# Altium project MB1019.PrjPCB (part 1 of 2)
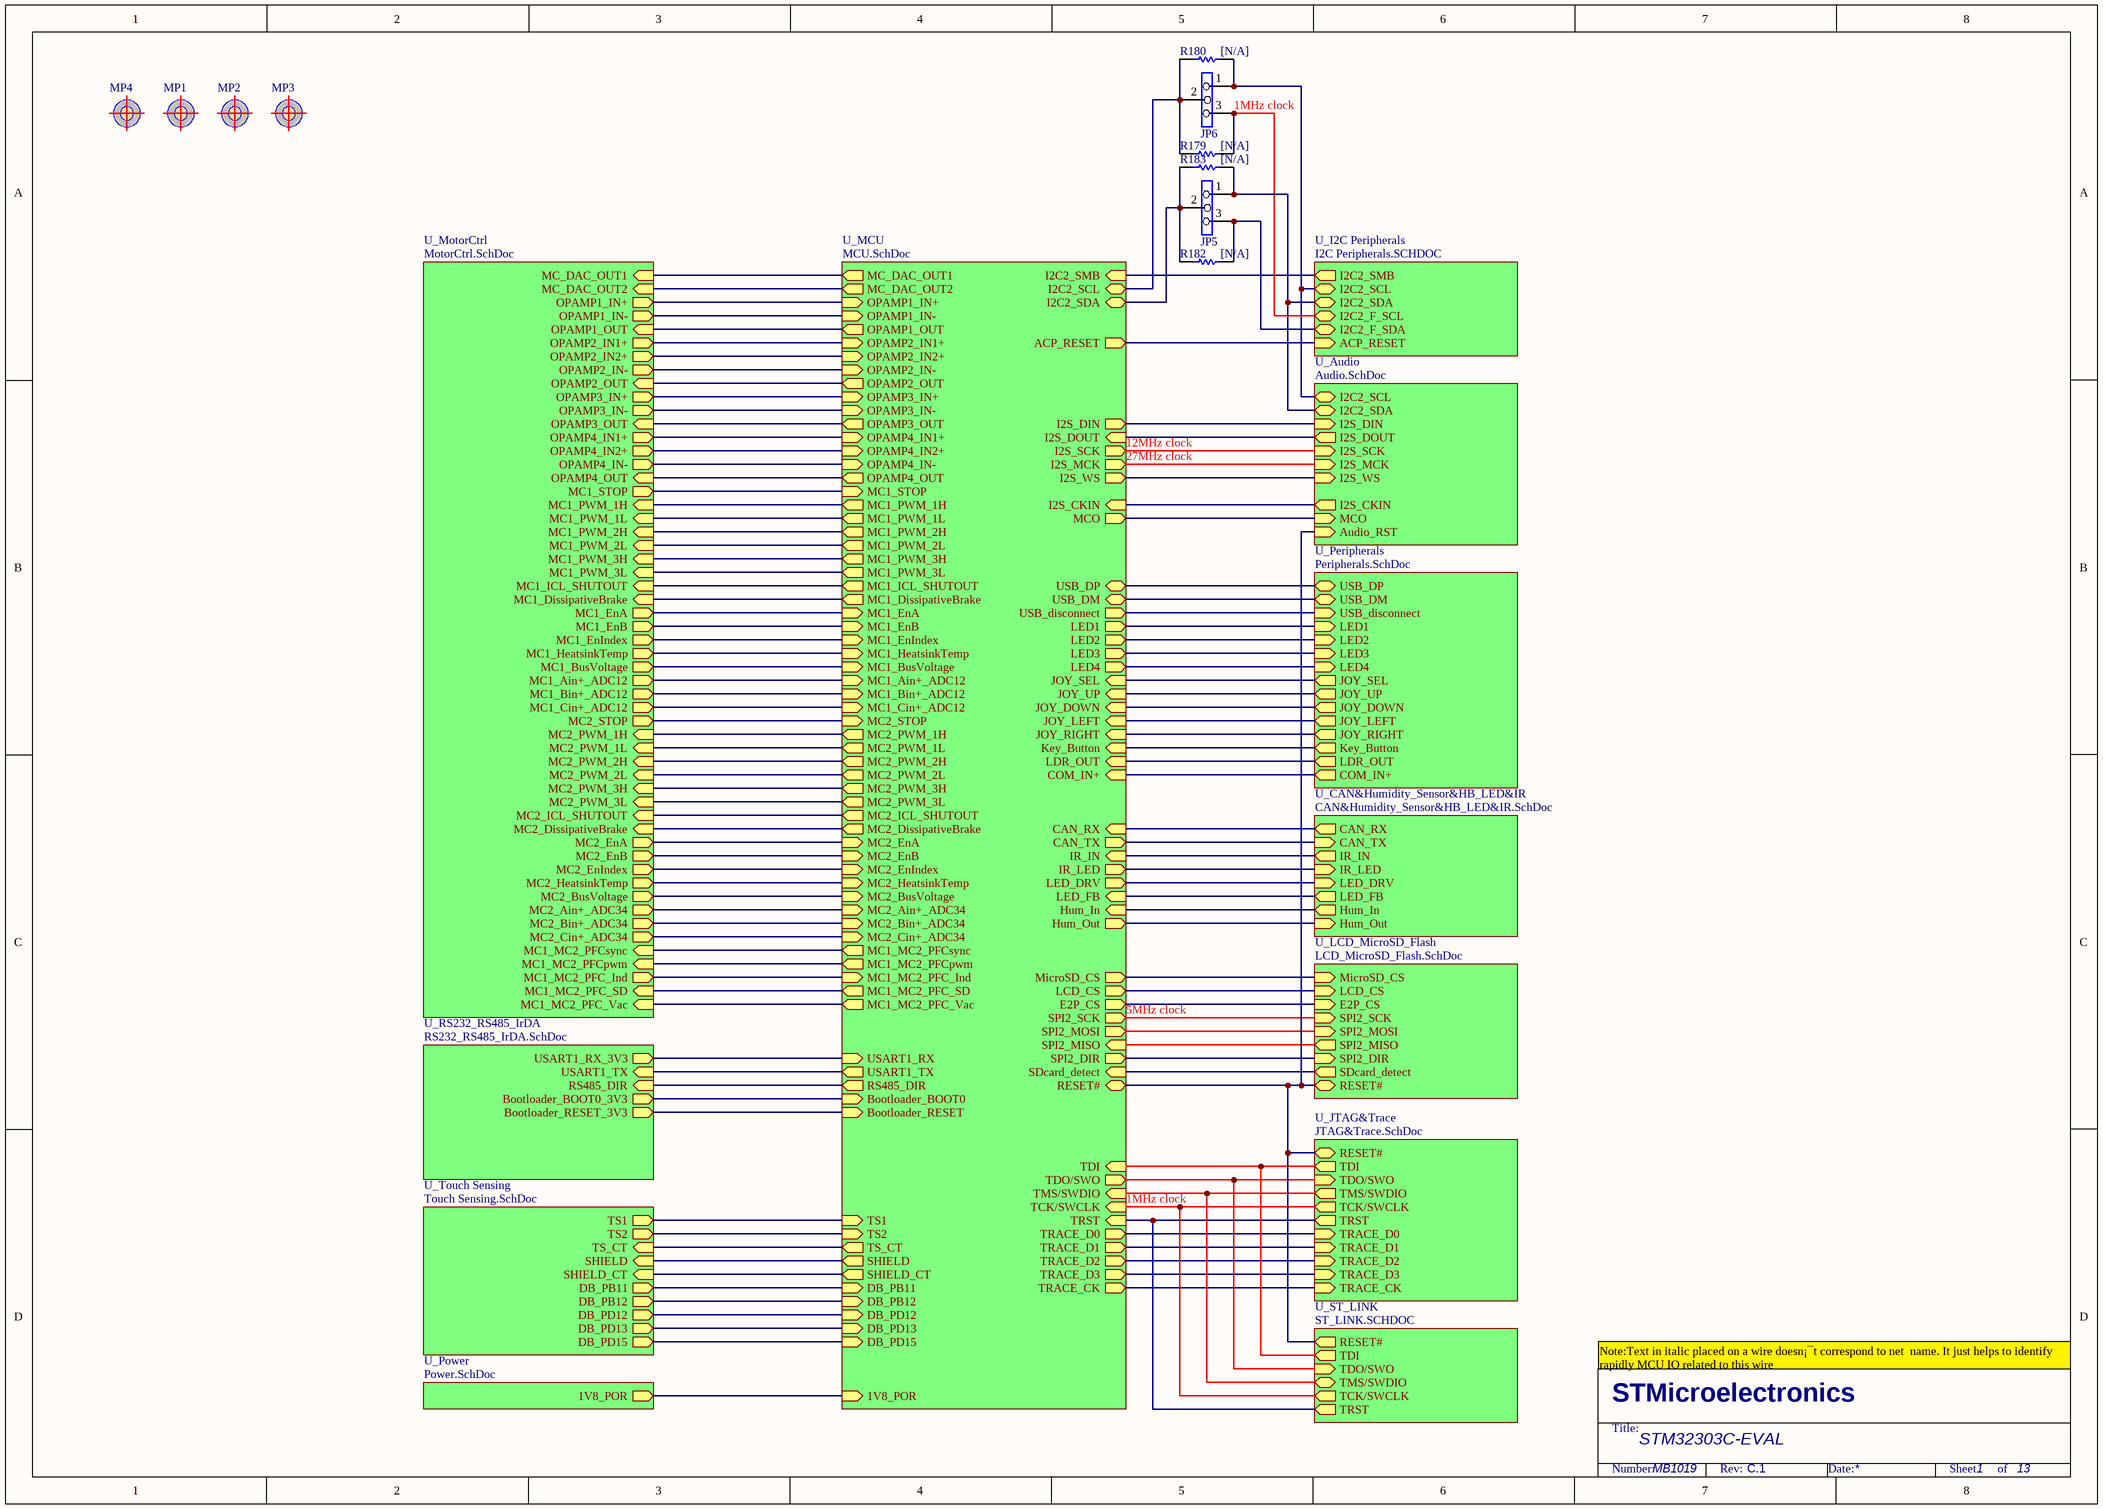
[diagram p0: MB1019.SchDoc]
13 sheets, 557 parts. Net scope: hierarchical (ports join the sheet entries above them; power ports are global).
Sheets:
  MB1019.SchDoc
    U_MCU = MCU.SchDoc
    U_MotorCtrl = MotorCtrl.SchDoc
    U_RS232_RS485_IrDA = RS232_RS485_IrDA.SchDoc
    U_Touch Sensing = Touch Sensing.SchDoc
    U_Peripherals = Peripherals.SchDoc
    U_CAN&Humidity_Sensor&HB_LED&IR = CAN&Humidity_Sensor&HB_LED&IR.SchDoc
    U_JTAG&Trace = JTAG&Trace.SchDoc
    U_ST_LINK = ST_LINK.SCHDOC
    U_Power = Power.SchDoc
    U_Audio = Audio.SchDoc
    U_I2C Peripherals = I2C Peripherals.SCHDOC
    U_LCD_MicroSD_Flash = LCD_MicroSD_Flash.SchDoc

## Sheet MB1019.SchDoc
size A3; Revision: C.1

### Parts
JP5  (no value)  [SIP3]
JP6  (no value)  [SIP3]
MP1  (no value)  [markpoint_1.0]
MP2  (no value)  [markpoint_1.0]
MP3  (no value)  [markpoint_1.0]
MP4  (no value)  [markpoint_1.0]
R179  [N/A]  [0603R]
R180  [N/A]  [0603R]
R182  [N/A]  [0603R]
R183  [N/A]  [0603R]

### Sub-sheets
U_Audio = Audio.SchDoc: I2S_WS (in), I2S_DIN (in), I2S_SCK (in), Audio_RST (in), I2S_MCK (in), MCO (in), I2S_CKIN (out), I2C2_SCL (bidir), I2C2_SDA (bidir), I2S_DOUT (out)
U_CAN&Humidity_Sensor&HB_LED&IR = CAN&Humidity_Sensor&HB_LED&IR.SchDoc: CAN_TX (in), CAN_RX (out), IR_LED (in), IR_IN (out), LED_DRV (in), LED_FB (out), Hum_Out (in), Hum_In (out)
U_I2C Peripherals = I2C Peripherals.SCHDOC: I2C2_SCL (bidir), I2C2_SDA (bidir), I2C2_SMB (out), I2C2_F_SDA (bidir), I2C2_F_SCL (bidir), ACP_RESET (in)
U_JTAG&Trace = JTAG&Trace.SchDoc: TDI (out), RESET# (bidir), TRACE_D3 (in), TRACE_D2 (in), TRACE_D1 (in), TRACE_D0 (in), TRACE_CK (in), TRST (out), TMS/SWDIO (out), TCK/SWCLK (out), TDO/SWO (in)
U_LCD_MicroSD_Flash = LCD_MicroSD_Flash.SchDoc: MicroSD_CS (in), SPI2_SCK (in), SPI2_MOSI (in), LCD_CS (in), SDcard_detect (out), RESET# (bidir), E2P_CS (in), SPI2_MISO (out), SPI2_DIR (in)
U_MCU = MCU.SchDoc: USB_DM (bidir), I2C2_SCL (bidir), I2C2_SDA (bidir), TMS/SWDIO (in), TCK/SWCLK (in), TDI (in), COM_IN+ (in), TDO/SWO (out), TRST (in), IR_IN (in), IR_LED (out), SPI2_MISO (in), SPI2_MOSI (out), RESET# (bidir), LDR_OUT (in), SPI2_SCK (out), USART1_RX (in), USART1_TX (out), LED4 (out), LED3 (out), LED1 (out), LED2 (out), Bootloader_BOOT0 (in), Bootloader_RESET (in), I2C2_SMB (in), USB_DP (bidir), CAN_RX (in), CAN_TX (out), MicroSD_CS (out), TRACE_D0 (out), TRACE_D1 (out), Key_Button (in), JOY_SEL (in), JOY_DOWN (in), JOY_LEFT (in), JOY_UP (in), JOY_RIGHT (in), TRACE_CK (out), E2P_CS (out), LCD_CS (out), TRACE_D2 (out), TRACE_D3 (out), SDcard_detect (in), DB_PD13 (in), DB_PD15 (in), 1V8_POR (in), USB_disconnect (out), MC2_HeatsinkTemp (in), OPAMP1_IN+ (in), OPAMP2_IN1+ (in), OPAMP3_IN+ (in), OPAMP3_OUT (out), OPAMP3_IN- (in), MC2_EnA (in), MC2_STOP (in), MC2_EnIndex (in), OPAMP4_IN- (in), OPAMP4_OUT (out), OPAMP4_IN1+ (in), MC1_Cin+_ADC12 (in), MC1_Ain+_ADC12 (in), MC1_Bin+_ADC12 (in), MC2_PWM_1H (out), MC2_PWM_2H (out), MC2_PWM_3H (out), MC2_PWM_1L (out), MC2_PWM_2L (out), MC2_PWM_3L (out), MC1_MC2_PFC_SD (out), MC1_EnA (in), MC1_EnB (in), MC1_EnIndex (in), MC1_MC2_PFC_Ind (in), MC2_EnB (in), MC1_MC2_PFCsync (out), MC1_MC2_PFCpwm (out), MC1_ICL_SHUTOUT (out), MC1_DissipativeBrake (out), MC1_PWM_1H (out), MC1_PWM_2H (out), MC1_PWM_3H (out), MC1_PWM_1L (out), MC1_PWM_2L (out), MC1_PWM_3L (out), LED_DRV (out), MC1_STOP (in), LED_FB (in), MC1_HeatsinkTemp (in), MC2_ICL_SHUTOUT (out), MC2_DissipativeBrake (out), MC1_MC2_PFC_Vac (out), MC2_BusVoltage (in), MC_DAC_OUT1 (out), MC_DAC_OUT2 (out), OPAMP1_OUT (out), OPAMP1_IN- (in), OPAMP2_OUT (out), OPAMP4_IN2+ (in), OPAMP2_IN2+ (in), MC1_BusVoltage (in), RS485_DIR (out), Hum_Out (out), TS2 (in), Hum_In (in), I2S_WS (out), SHIELD (out), OPAMP2_IN- (in), MC2_Cin+_ADC34 (in), MC2_Ain+_ADC34 (in), MC2_Bin+_ADC34 (in), TS_CT (out), TS1 (in), DB_PB12 (in), SHIELD_CT (out), DB_PD12 (in), DB_PB11 (in), ACP_RESET (out), I2S_CKIN (in), MCO (out), I2S_DIN (out), I2S_SCK (out), I2S_MCK (out), I2S_DOUT (in), SPI2_DIR (out)
U_MotorCtrl = MotorCtrl.SchDoc: MC1_STOP (out), MC1_MC2_PFCsync (in), MC1_ICL_SHUTOUT (in), MC1_DissipativeBrake (in), MC1_MC2_PFCpwm (in), MC1_EnA (out), MC1_EnB (out), MC1_HeatsinkTemp (out), MC1_BusVoltage (out), MC1_EnIndex (out), MC1_PWM_1H (in), MC1_PWM_2H (in), MC1_PWM_3H (in), MC1_PWM_1L (in), MC1_PWM_2L (in), MC1_PWM_3L (in), MC1_MC2_PFC_Ind (out), MC1_MC2_PFC_Vac (in), MC1_MC2_PFC_SD (in), MC2_STOP (out), MC2_ICL_SHUTOUT (in), MC2_DissipativeBrake (in), MC2_EnA (out), MC2_EnB (out), MC2_HeatsinkTemp (out), MC2_BusVoltage (out), MC2_EnIndex (out), MC2_PWM_1H (in), MC2_PWM_2H (in), MC2_PWM_3H (in), MC2_PWM_1L (in), MC2_PWM_2L (in), MC2_PWM_3L (in), OPAMP1_IN+ (out), OPAMP1_IN- (out), OPAMP1_OUT (in), MC1_Ain+_ADC12 (out), MC_DAC_OUT2 (in), MC_DAC_OUT1 (in), OPAMP2_IN1+ (out), OPAMP2_IN- (out), OPAMP2_OUT (in), OPAMP2_IN2+ (out), OPAMP4_IN1+ (out), OPAMP4_IN- (out), OPAMP4_OUT (in), OPAMP4_IN2+ (out), OPAMP3_IN+ (out), OPAMP3_IN- (out), OPAMP3_OUT (in), MC1_Bin+_ADC12 (out), MC1_Cin+_ADC12 (out), MC2_Cin+_ADC34 (out), MC2_Bin+_ADC34 (out), MC2_Ain+_ADC34 (out)
U_Peripherals = Peripherals.SchDoc: JOY_SEL (out), JOY_DOWN (out), JOY_LEFT (out), JOY_RIGHT (out), JOY_UP (out), USB_DM (bidir), USB_DP (bidir), Key_Button (out), USB_disconnect (in), LDR_OUT (out), COM_IN+ (out), LED4 (in), LED3 (in), LED1 (in), LED2 (in)
U_Power = Power.SchDoc: 1V8_POR (out)
U_RS232_RS485_IrDA = RS232_RS485_IrDA.SchDoc: USART1_RX_3V3 (out), RS485_DIR (in), Bootloader_BOOT0_3V3 (out), Bootloader_RESET_3V3 (out), USART1_TX (in)
U_ST_LINK = ST_LINK.SCHDOC: TDI (out), TRST (out), TMS/SWDIO (bidir), TCK/SWCLK (out), TDO/SWO (in), RESET# (out)
U_Touch Sensing = Touch Sensing.SchDoc: TS1 (out), TS2 (out), SHIELD (in), SHIELD_CT (in), TS_CT (in), DB_PD13 (out), DB_PD15 (out), DB_PD12 (out), DB_PB11 (out), DB_PB12 (out)

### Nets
MC1_MC2_PFC_Ind: sheet U_MCU/MC1_MC2_PFC_Ind, sheet U_MotorCtrl/MC1_MC2_PFC_Ind
MC1_MC2_PFC_SD: sheet U_MCU/MC1_MC2_PFC_SD, sheet U_MotorCtrl/MC1_MC2_PFC_SD
MC1_MC2_PFC_Vac: sheet U_MCU/MC1_MC2_PFC_Vac, sheet U_MotorCtrl/MC1_MC2_PFC_Vac
MC1_MC2_PFCpwm: sheet U_MCU/MC1_MC2_PFCpwm, sheet U_MotorCtrl/MC1_MC2_PFCpwm
MC1_MC2_PFCsync: sheet U_MCU/MC1_MC2_PFCsync, sheet U_MotorCtrl/MC1_MC2_PFCsync
PA1: sheet U_MCU/OPAMP1_IN+, sheet U_MotorCtrl/OPAMP1_IN+
PA2: sheet U_MCU/OPAMP1_OUT, sheet U_MotorCtrl/OPAMP1_OUT
PA3: sheet U_MCU/OPAMP1_IN-, sheet U_MotorCtrl/OPAMP1_IN-
PA5: sheet U_MCU/MC_DAC_OUT2, sheet U_MotorCtrl/MC_DAC_OUT2
PA6: sheet U_MCU/OPAMP2_OUT, sheet U_MotorCtrl/OPAMP2_OUT
PA7: sheet U_MCU/OPAMP2_IN1+, sheet U_MotorCtrl/OPAMP2_IN1+
PA8: sheet U_MCU/MCO, sheet U_Audio/MCO
PA10: JP5.2 R182.2 R183.2 ; sheet U_MCU/I2C2_SDA
PA11: sheet U_MCU/USB_DM, sheet U_Peripherals/USB_DM
PA12: sheet U_MCU/USB_DP, sheet U_Peripherals/USB_DP
PA13: sheet U_MCU/TMS/SWDIO, sheet U_JTAG&Trace/TMS/SWDIO, sheet U_ST_LINK/TMS/SWDIO
PA14: sheet U_MCU/TCK/SWCLK, sheet U_JTAG&Trace/TCK/SWCLK, sheet U_ST_LINK/TCK/SWCLK
PA15: sheet U_MCU/TDI, sheet U_JTAG&Trace/TDI, sheet U_ST_LINK/TDI
PB1: sheet U_MCU/OPAMP3_OUT, sheet U_MotorCtrl/OPAMP3_OUT
PB2: sheet U_MCU/1V8_POR, sheet U_Power/1V8_POR
PB3: sheet U_MCU/TDO/SWO, sheet U_JTAG&Trace/TDO/SWO, sheet U_ST_LINK/TDO/SWO
PB4: sheet U_MCU/TRST, sheet U_JTAG&Trace/TRST, sheet U_ST_LINK/TRST
PB5: sheet U_MCU/JOY_LEFT, sheet U_Peripherals/JOY_LEFT
PB6: sheet U_MCU/MC2_EnA, sheet U_MotorCtrl/MC2_EnA
PB7: sheet U_MCU/MC2_STOP, sheet U_MotorCtrl/MC2_STOP
PB9: sheet U_MCU/IR_LED, sheet U_CAN&Humidity_Sensor&HB_LED&IR/IR_LED
PB10: sheet U_MCU/OPAMP4_IN-, sheet U_MotorCtrl/OPAMP4_IN-
PB13: sheet U_MCU/OPAMP4_IN2+, sheet U_MotorCtrl/OPAMP4_IN2+
PB14: sheet U_MCU/SPI2_MISO, sheet U_LCD_MicroSD_Flash/SPI2_MISO
PB15: sheet U_MCU/SPI2_MOSI, sheet U_LCD_MicroSD_Flash/SPI2_MOSI
PC0: sheet U_MCU/MC1_Cin+_ADC12, sheet U_MotorCtrl/MC1_Cin+_ADC12
PC2: sheet U_MCU/MC1_Ain+_ADC12, sheet U_MotorCtrl/MC1_Ain+_ADC12
PC3: sheet U_MCU/MC1_Bin+_ADC12, sheet U_MotorCtrl/MC1_Bin+_ADC12
PC4: sheet U_MCU/USART1_TX, sheet U_RS232_RS485_IrDA/USART1_TX
PC5: sheet U_MCU/OPAMP2_IN-, sheet U_MotorCtrl/OPAMP2_IN-
PC7: sheet U_MCU/MC2_PWM_2H, sheet U_MotorCtrl/MC2_PWM_2H
PC9: sheet U_MCU/I2S_CKIN, sheet U_Audio/I2S_CKIN
PC13: sheet U_MCU/JOY_SEL, sheet U_Peripherals/JOY_SEL
PD0: sheet U_MCU/CAN_RX, sheet U_CAN&Humidity_Sensor&HB_LED&IR/CAN_RX
PD1: sheet U_MCU/CAN_TX, sheet U_CAN&Humidity_Sensor&HB_LED&IR/CAN_TX
PD3: sheet U_MCU/MC1_EnA, sheet U_MotorCtrl/MC1_EnA
PD4: sheet U_MCU/MC1_EnB, sheet U_MotorCtrl/MC1_EnB
PD5: sheet U_MCU/JOY_DOWN, sheet U_Peripherals/JOY_DOWN
PD6: sheet U_MCU/JOY_RIGHT, sheet U_Peripherals/JOY_RIGHT
PD10: sheet U_MCU/MC2_Cin+_ADC34, sheet U_MotorCtrl/MC2_Cin+_ADC34
PD11: sheet U_MCU/MC2_Ain+_ADC34, sheet U_MotorCtrl/MC2_Ain+_ADC34
PE0: sheet U_MCU/LCD_CS, sheet U_LCD_MicroSD_Flash/LCD_CS
PE1: sheet U_MCU/USART1_RX, sheet U_RS232_RS485_IrDA/USART1_RX_3V3
PE6: sheet U_MCU/TRACE_D3, sheet U_JTAG&Trace/TRACE_D3
PE7: sheet U_MCU/JOY_UP, sheet U_Peripherals/JOY_UP
PE12: sheet U_MCU/MC1_PWM_3L, sheet U_MotorCtrl/MC1_PWM_3L
PE14: sheet U_MCU/ACP_RESET, sheet U_MCU/SPI2_DIR, sheet U_I2C Peripherals/ACP_RESET, sheet U_LCD_MicroSD_Flash/SPI2_DIR
PF4: sheet U_MCU/MC1_HeatsinkTemp, sheet U_MotorCtrl/MC1_HeatsinkTemp
PF6: JP6.2 R179.2 R180.2 ; sheet U_MCU/I2C2_SCL
PF9: sheet U_MCU/SPI2_SCK, sheet U_LCD_MicroSD_Flash/SPI2_SCK
PF10: sheet U_MCU/MC2_DissipativeBrake, sheet U_MotorCtrl/MC2_DissipativeBrake
RESET#: sheet U_MCU/RESET#, sheet U_JTAG&Trace/RESET#, sheet U_ST_LINK/RESET#, sheet U_Audio/Audio_RST, sheet U_LCD_MicroSD_Flash/RESET#
NetC2_2: sheet U_MCU/MC1_STOP, sheet U_MotorCtrl/MC1_STOP
NetC3_1: sheet U_MCU/MC1_BusVoltage, sheet U_MotorCtrl/MC1_BusVoltage
NetC13_2: sheet U_MCU/MC1_EnIndex, sheet U_MotorCtrl/MC1_EnIndex
NetC14_1: sheet U_MCU/MC2_BusVoltage, sheet U_MotorCtrl/MC2_BusVoltage
NetC19_2: sheet U_MCU/MC2_HeatsinkTemp, sheet U_MotorCtrl/MC2_HeatsinkTemp
NetC21_1: sheet U_MCU/OPAMP4_OUT, sheet U_MotorCtrl/OPAMP4_OUT
NetC27_2: sheet U_MCU/MC2_EnB, sheet U_MotorCtrl/MC2_EnB
NetC28_2: sheet U_MCU/MC2_EnIndex, sheet U_MotorCtrl/MC2_EnIndex
NetC29_2: sheet U_MCU/OPAMP3_IN-, sheet U_MotorCtrl/OPAMP3_IN-
NetC52_2: sheet U_MCU/TS_CT, sheet U_Touch Sensing/TS_CT
NetC68_1: sheet U_MCU/LED_FB, sheet U_CAN&Humidity_Sensor&HB_LED&IR/LED_FB
NetC133_1: sheet U_MCU/OPAMP2_IN2+, sheet U_MotorCtrl/OPAMP2_IN2+
NetC134_1: sheet U_MCU/OPAMP4_IN1+, sheet U_MotorCtrl/OPAMP4_IN1+
NetC136_1: sheet U_MCU/OPAMP3_IN+, sheet U_MotorCtrl/OPAMP3_IN+
NetCN2_3: sheet U_MCU/MC1_PWM_1H, sheet U_MotorCtrl/MC1_PWM_1H
NetCN2_5: sheet U_MCU/MC1_PWM_1L, sheet U_MotorCtrl/MC1_PWM_1L
NetCN2_7: sheet U_MCU/MC1_PWM_2H, sheet U_MotorCtrl/MC1_PWM_2H
NetCN2_9: sheet U_MCU/MC1_PWM_2L, sheet U_MotorCtrl/MC1_PWM_2L
NetCN2_11: sheet U_MCU/MC1_PWM_3H, sheet U_MotorCtrl/MC1_PWM_3H
NetCN2_21: sheet U_MCU/MC1_ICL_SHUTOUT, sheet U_MotorCtrl/MC1_ICL_SHUTOUT
NetCN2_23: sheet U_MCU/MC1_DissipativeBrake, sheet U_MotorCtrl/MC1_DissipativeBrake
NetCN4_3: sheet U_MCU/MC2_PWM_1H, sheet U_MotorCtrl/MC2_PWM_1H
NetCN4_5: sheet U_MCU/MC2_PWM_1L, sheet U_MotorCtrl/MC2_PWM_1L
NetCN4_9: sheet U_MCU/MC2_PWM_2L, sheet U_MotorCtrl/MC2_PWM_2L
NetCN4_11: sheet U_MCU/MC2_PWM_3H, sheet U_MotorCtrl/MC2_PWM_3H
NetCN4_13: sheet U_MCU/MC2_PWM_3L, sheet U_MotorCtrl/MC2_PWM_3L
NetCN4_21: sheet U_MCU/MC2_ICL_SHUTOUT, sheet U_MotorCtrl/MC2_ICL_SHUTOUT
NetCN6_51: sheet U_MCU/DB_PB11, sheet U_Touch Sensing/DB_PB11
NetCN6_52: sheet U_MCU/DB_PB12, sheet U_Touch Sensing/DB_PB12
NetCN7_2: sheet U_MCU/DB_PD15, sheet U_Touch Sensing/DB_PD15
NetCN7_4: sheet U_MCU/DB_PD13, sheet U_Touch Sensing/DB_PD13
NetCN7_6: sheet U_MCU/DB_PD12, sheet U_Touch Sensing/DB_PD12
NetCN9_12: sheet U_MCU/TRACE_CK, sheet U_JTAG&Trace/TRACE_CK
NetCN9_18: sheet U_MCU/TRACE_D2, sheet U_JTAG&Trace/TRACE_D2
NetCN16_2: sheet U_MCU/MicroSD_CS, sheet U_LCD_MicroSD_Flash/MicroSD_CS
NetCN16_10: sheet U_MCU/SDcard_detect, sheet U_LCD_MicroSD_Flash/SDcard_detect
NetD2_1: sheet U_MCU/Bootloader_BOOT0, sheet U_RS232_RS485_IrDA/Bootloader_BOOT0_3V3
NetJP1_2: sheet U_MCU/I2C2_SMB, sheet U_I2C Peripherals/I2C2_SMB
NetJP5_1: JP5.1 R183.1 ; sheet U_Audio/I2C2_SDA, sheet U_I2C Peripherals/I2C2_SDA
NetJP5_3: JP5.3 R182.1 ; sheet U_I2C Peripherals/I2C2_F_SDA
NetJP6_1: JP6.1 R180.1 ; sheet U_Audio/I2C2_SCL, sheet U_I2C Peripherals/I2C2_SCL
NetJP6_3: JP6.3 R179.1 ; sheet U_I2C Peripherals/I2C2_F_SCL
NetJP10_2: sheet U_MCU/Bootloader_RESET, sheet U_RS232_RS485_IrDA/Bootloader_RESET_3V3
NetJP18_1: sheet U_MCU/I2S_MCK, sheet U_Audio/I2S_MCK
NetJP18_3: sheet U_MCU/IR_IN, sheet U_CAN&Humidity_Sensor&HB_LED&IR/IR_IN
NetJP19_2: sheet U_MCU/Hum_In, sheet U_CAN&Humidity_Sensor&HB_LED&IR/Hum_In
NetPG3SA_2: sheet U_MCU/MC_DAC_OUT1, sheet U_MotorCtrl/MC_DAC_OUT1
NetR4_1: sheet U_MCU/TRACE_D0, sheet U_JTAG&Trace/TRACE_D0
NetR6_1: sheet U_MCU/TRACE_D1, sheet U_JTAG&Trace/TRACE_D1
NetR10_2: sheet U_MCU/LDR_OUT, sheet U_Peripherals/LDR_OUT
NetR14_1: sheet U_MCU/COM_IN+, sheet U_Peripherals/COM_IN+
NetR16_2: sheet U_MCU/I2S_WS, sheet U_Audio/I2S_WS
NetR18_2: sheet U_MCU/USB_disconnect, sheet U_Peripherals/USB_disconnect
NetR24_1: sheet U_MCU/LED1, sheet U_Peripherals/LED1
NetR26_1: sheet U_MCU/LED2, sheet U_Peripherals/LED2
NetR28_1: sheet U_MCU/LED3, sheet U_Peripherals/LED3
NetR30_1: sheet U_MCU/LED4, sheet U_Peripherals/LED4
NetR32_1: sheet U_MCU/LED_DRV, sheet U_CAN&Humidity_Sensor&HB_LED&IR/LED_DRV
NetR36_2: sheet U_MCU/SHIELD_CT, sheet U_Touch Sensing/SHIELD_CT
NetR38_2: sheet U_MCU/SHIELD, sheet U_Touch Sensing/SHIELD
NetR39_1: sheet U_MCU/MC2_Bin+_ADC34, sheet U_MotorCtrl/MC2_Bin+_ADC34
NetR42_1: sheet U_MCU/TS1, sheet U_Touch Sensing/TS1
NetR44_1: sheet U_MCU/TS2, sheet U_Touch Sensing/TS2
NetR50_1: sheet U_MCU/Hum_Out, sheet U_CAN&Humidity_Sensor&HB_LED&IR/Hum_Out
NetR52_1: sheet U_MCU/I2S_SCK, sheet U_Audio/I2S_SCK
NetR54_1: sheet U_MCU/I2S_DOUT, sheet U_Audio/I2S_DOUT
NetR56_1: sheet U_MCU/I2S_DIN, sheet U_Audio/I2S_DIN
NetR58_1: sheet U_MCU/E2P_CS, sheet U_LCD_MicroSD_Flash/E2P_CS
NetR111_1: sheet U_MCU/Key_Button, sheet U_Peripherals/Key_Button
NetR129_1: sheet U_MCU/RS485_DIR, sheet U_RS232_RS485_IrDA/RS485_DIR

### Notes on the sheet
- (near JP6) 1MHz clock
- 12MHz clock
- 27MHz clock
- 5MHz clock
- 1MHz clock
- Note:Text in italic placed on a wire doesn¡¯t correspond to net  name. It just helps to identify rapidly MCU IO related to this wire
- STM32303C-EVAL
- MB1019
- 1
- 13

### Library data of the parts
JP5 JP6 = Jumper3
MP1-MP4 = MARKPOINT
R179 R180 R182 R183 = Res1: Resistor; Value: 1K

## Sheet MCU.SchDoc
size A4; Revision: C.1
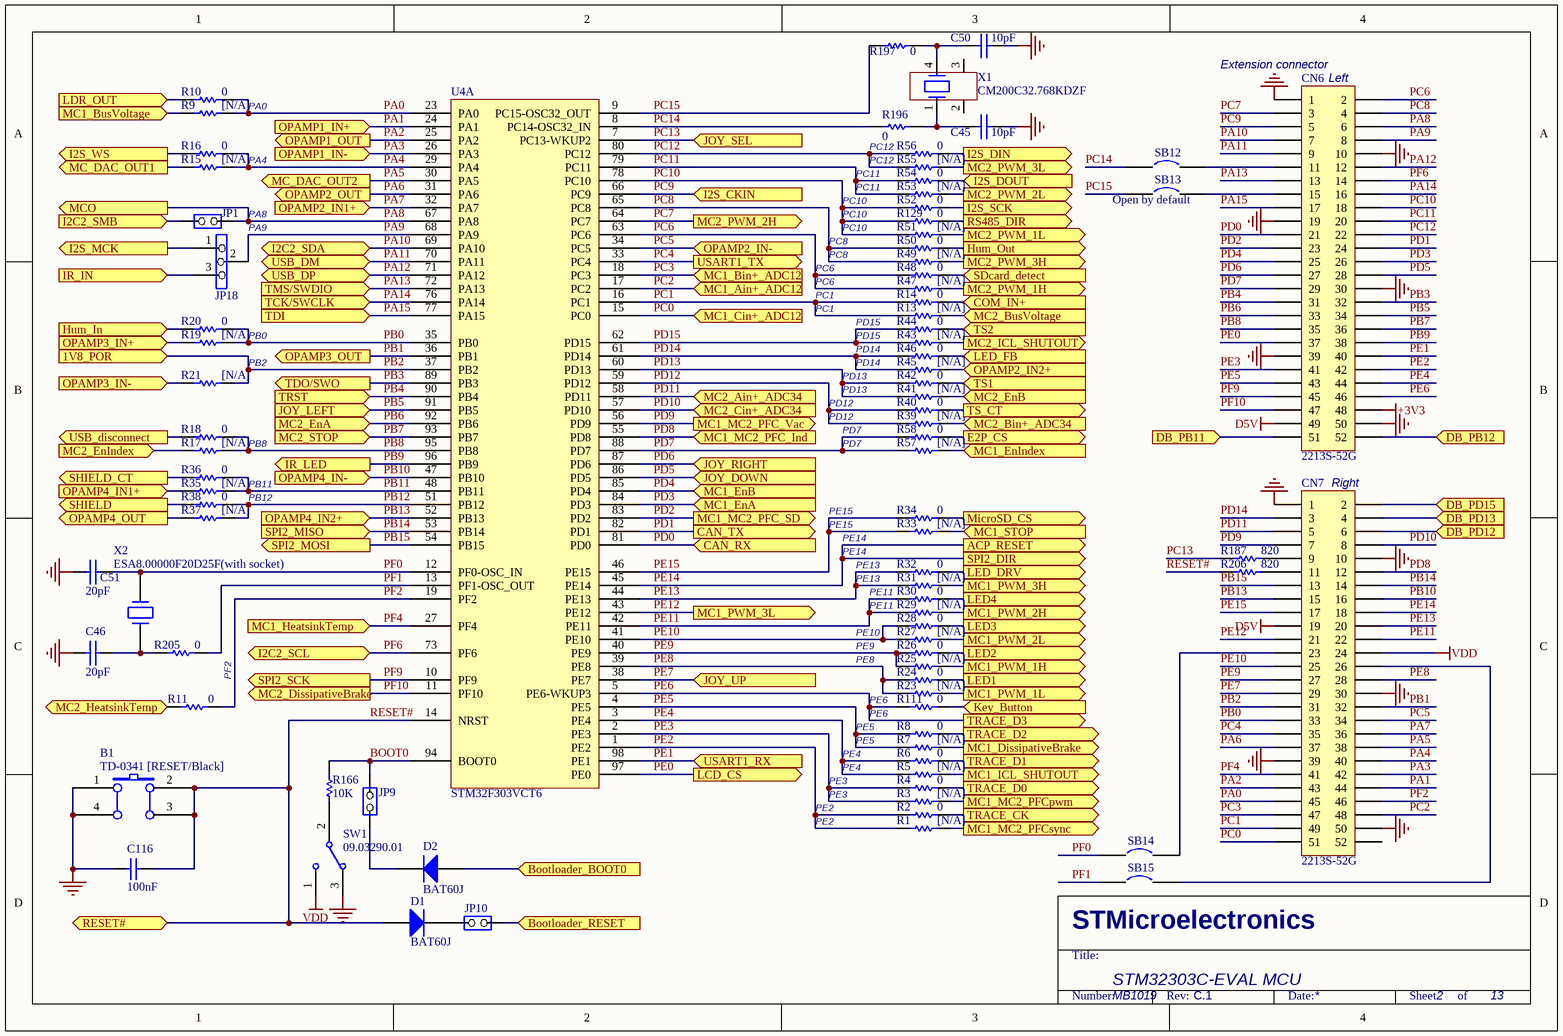
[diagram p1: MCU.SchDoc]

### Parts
B1  TD-0341 [RESET/Black]  [PB10]
C45  10pF  [0603C]
C46  20pF  [0603C]
C50  10pF  [0603C]
C51  20pF  [0603C]
C116  100nF  [0603C]
CN6  2213S-52G  [2*26P]
CN7  2213S-52G  [2*26P]
D1  BAT60J  [SOD-323]
D2  BAT60J  [SOD-323]
JP1  (no value)  [SIP2]
JP9  (no value)  [SIP2]
JP10  (no value)  [SIP2]
JP18  (no value)  [SIP3]
R1  [N/A]  [0603R]
R2  0  [0603R]
R3  [N/A]  [0603R]
R4  0  [0603R]
R5  [N/A]  [0603R]
R6  0  [0603R]
R7  [N/A]  [0603R]
R8  0  [0603R]
R9  [N/A]  [0603R]
R10  0  [0603R]
R11  0  [0603R]
R13  [N/A]  [0603R]
R14  0  [0603R]
R15  [N/A]  [0603R]
R16  0  [0603R]
R17  [N/A]  [0603R]
R18  0  [0603R]
R19  [N/A]  [0603R]
R20  0  [0603R]
R21  [N/A]  [0603R]
R23  [N/A]  [0603R]
R24  0  [0603R]
R25  [N/A]  [0603R]
R26  0  [0603R]
R27  [N/A]  [0603R]
R28  0  [0603R]
R29  [N/A]  [0603R]
R30  0  [0603R]
R31  [N/A]  [0603R]
R32  0  [0603R]
R33  [N/A]  [0603R]
R34  0  [0603R]
R35  [N/A]  [0603R]
R36  0  [0603R]
R37  [N/A]  [0603R]
R38  0  [0603R]
R39  [N/A]  [0603R]
R40  0  [0603R]
R41  [N/A]  [0603R]
R42  0  [0603R]
R43  [N/A]  [0603R]
R44  0  [0603R]
R45  [N/A]  [0603R]
R46  0  [0603R]
R47  [N/A]  [0603R]
R48  0  [0603R]
R49  [N/A]  [0603R]
R50  0  [0603R]
R51  [N/A]  [0603R]
R52  0  [0603R]
R53  [N/A]  [0603R]
R54  0  [0603R]
R55  [N/A]  [0603R]
R56  0  [0603R]
R57  [N/A]  [0603R]
R58  0  [0603R]
R111  0  [0603R]
R129  0  [0603R]
R166  10K  [0603R]
R187  820  [0603R]
R196  0  [0603R]
R197  0  [0603R]
R205  0  [0603R]
R206  820  [0603R]
SB12  (no value)  [JP2_SMD]
SB13  (no value)  [JP2_SMD]
SB14  (no value)  [JP2_SMD]
SB15  (no value)  [JP2_SMD]
SW1  09.03290.01  [SIP3]
U4  STM32F303VCT6  [IC149-100-025-B5]  (part A of 2)
X1  CM200C32.768KDZF  [SM8]
X2  ESA8.00000F20D25F(with socket)  [XTAL_socket]

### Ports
1V8_POR (in), ACP_RESET (out), Bootloader_BOOT0 (in), Bootloader_RESET (in), CAN_RX (in), CAN_TX (out), COM_IN+ (in), DB_PB11 (in), DB_PB12 (in), DB_PD12 (in), DB_PD13 (in), DB_PD15 (in), E2P_CS (out), Hum_In (in), Hum_Out (out), I2C2_SCL (bidir), I2C2_SDA (bidir), I2C2_SMB (in), I2S_CKIN (in), I2S_DIN (out), I2S_DOUT (in), I2S_MCK (out), I2S_SCK (out), I2S_WS (out), IR_IN (in), IR_LED (out), JOY_DOWN (in), JOY_LEFT (in), JOY_RIGHT (in), JOY_SEL (in), JOY_UP (in), Key_Button (in), LCD_CS (out), LDR_OUT (in), LED1 (out), LED2 (out), LED3 (out), LED4 (out), LED_DRV (out), LED_FB (in), MC1_Ain+_ADC12 (in), MC1_Bin+_ADC12 (in), MC1_BusVoltage (in), MC1_Cin+_ADC12 (in), MC1_DissipativeBrake (out), MC1_EnA (in), MC1_EnB (in), MC1_EnIndex (in), MC1_HeatsinkTemp (in), MC1_ICL_SHUTOUT (out), MC1_MC2_PFC_Ind (in), MC1_MC2_PFC_SD (out), MC1_MC2_PFC_Vac (out), MC1_MC2_PFCpwm (out), MC1_MC2_PFCsync (out), MC1_PWM_1H (out), MC1_PWM_1L (out), MC1_PWM_2H (out), MC1_PWM_2L (out), MC1_PWM_3H (out), MC1_PWM_3L (out), MC1_STOP (in), MC2_Ain+_ADC34 (in), MC2_Bin+_ADC34 (in), MC2_BusVoltage (in), MC2_Cin+_ADC34 (in), MC2_DissipativeBrake (out), MC2_EnA (in), MC2_EnB (in), MC2_EnIndex (in), MC2_HeatsinkTemp (in), MC2_ICL_SHUTOUT (out), MC2_PWM_1H (out), MC2_PWM_1L (out), MC2_PWM_2H (out), MC2_PWM_2L (out), MC2_PWM_3H (out), MC2_PWM_3L (out), MC2_STOP (in), MC_DAC_OUT1 (out), MC_DAC_OUT2 (out), MCO (out), MicroSD_CS (out), OPAMP1_IN+ (in), OPAMP1_IN- (in), OPAMP1_OUT (out), OPAMP2_IN1+ (in), OPAMP2_IN2+ (in), OPAMP2_IN- (in), OPAMP2_OUT (out), OPAMP3_IN+ (in), OPAMP3_IN- (in), OPAMP3_OUT (out), OPAMP4_IN1+ (in), OPAMP4_IN2+ (in), OPAMP4_IN- (in), OPAMP4_OUT (out), RESET# (bidir), RS485_DIR (out), SDcard_detect (in), SHIELD (out), SHIELD_CT (out), SPI2_DIR (out), SPI2_MISO (in), SPI2_MOSI (out), SPI2_SCK (out), TCK/SWCLK (in), TDI (in), TDO/SWO (out), TMS/SWDIO (in), TRACE_CK (out), TRACE_D0 (out), TRACE_D1 (out), TRACE_D2 (out), TRACE_D3 (out), TRST (in), TS1 (in), TS2 (in), TS_CT (out), USART1_RX (in), USART1_TX (out), USB_disconnect (out), USB_DM (bidir), USB_DP (bidir)

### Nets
+3V3: CN6.48
D5V: CN6.49 CN7.19
GND: B1.1(A0) B1.4(A1) C45.2 C46.2 C50.2 C51.2 C116.1 CN6.1 CN6.10 CN6.19 CN6.30 CN6.39 CN6.50 CN7.1 CN7.10 CN7.30 CN7.39 CN7.50 SW1.3
VDD: CN7.24 SW1.1
BOOT0: JP9.2(NO) R166.1 U4.94(BOOT0)
MC1_MC2_PFCpwm: R3.1 ; port MC1_MC2_PFCpwm
MC1_MC2_PFCsync: R1.1 ; port MC1_MC2_PFCsync
PA0: CN7.45 R9.1 R10.1 U4.23(PA0)
PA1: CN7.44 U4.24(PA1) ; port OPAMP1_IN+
PA2: CN7.43 U4.25(PA2) ; port OPAMP1_OUT
PA3: CN7.42 U4.26(PA3) ; port OPAMP1_IN-
PA4: CN7.40 R15.1 R16.1 U4.29(PA4)
PA5: CN7.38 U4.30(PA5) ; port MC_DAC_OUT2
PA6: CN7.37 U4.31(PA6) ; port OPAMP2_OUT
PA7: CN7.36 U4.32(PA7) ; port OPAMP2_IN1+
PA8: CN6.6 JP1.1(COMMON) U4.67(PA8) ; port MCO
PA9: CN6.8 JP18.2 U4.68(PA9)
PA10: CN6.7 U4.69(PA10) ; port I2C2_SDA
PA11: CN6.9 U4.70(PA11) ; port USB_DM
PA12: CN6.12 U4.71(PA12) ; port USB_DP
PA13: CN6.13 U4.72(PA13) ; port TMS/SWDIO
PA14: CN6.16 U4.76(PA14) ; port TCK/SWCLK
PA15: CN6.17 U4.77(PA15) ; port TDI
PB0: CN7.33 R19.1 R20.1 U4.35(PB0)
PB1: CN7.32 U4.36(PB1) ; port OPAMP3_OUT
PB2: CN7.31 R21.1 U4.37(PB2) ; port 1V8_POR
PB3: CN6.32 U4.89(PB3) ; port TDO/SWO
PB4: CN6.31 U4.90(PB4) ; port TRST
PB5: CN6.34 U4.91(PB5) ; port JOY_LEFT
PB6: CN6.33 U4.92(PB6) ; port MC2_EnA
PB7: CN6.36 U4.93(PB7) ; port MC2_STOP
PB8: CN6.35 R17.1 R18.1 U4.95(PB8)
PB9: CN6.38 U4.96(PB9) ; port IR_LED
PB10: CN7.16 U4.47(PB10) ; port OPAMP4_IN-
PB11: R35.1 R36.1 U4.48(PB11)
PB12: R37.1 R38.1 U4.51(PB12)
PB13: CN7.15 U4.52(PB13) ; port OPAMP4_IN2+
PB14: CN7.14 U4.53(PB14) ; port SPI2_MISO
PB15: CN7.13 U4.54(PB15) ; port SPI2_MOSI
PC0: CN7.51 U4.15(PC0) ; port MC1_Cin+_ADC12
PC1: CN7.49 R13.2 R14.2 U4.16(PC1)
PC2: CN7.48 U4.17(PC2) ; port MC1_Ain+_ADC12
PC3: CN7.47 U4.18(PC3) ; port MC1_Bin+_ADC12
PC4: CN7.35 U4.33(PC4) ; port USART1_TX
PC5: CN7.34 U4.34(PC5) ; port OPAMP2_IN-
PC6: CN6.2 R47.2 R48.2 U4.63(PC6)
PC7: CN6.3 U4.64(PC7) ; port MC2_PWM_2H
PC8: CN6.4 R49.2 R50.2 U4.65(PC8)
PC9: CN6.5 U4.66(PC9) ; port I2S_CKIN
PC10: CN6.18 R51.2 R52.2 R129.2 U4.78(PC10)
PC11: CN6.20 R53.2 R54.2 U4.79(PC11)
PC12: CN6.22 R55.2 R56.2 U4.80(PC12)
PC13: R187.1 U4.7(PC13-WKUP2) ; port JOY_SEL
PC14: R196.2 SB12.1 U4.8(PC14-OSC32_IN)
PC15: R197.2 SB13.1 U4.9(PC15-OSC32_OUT)
PD0: CN6.21 U4.81(PD0) ; port CAN_RX
PD1: CN6.24 U4.82(PD1) ; port CAN_TX
PD2: CN6.23 U4.83(PD2) ; port MC1_MC2_PFC_SD  [project net MC1_MC2_PFC_SD]
PD3: CN6.26 U4.84(PD3) ; port MC1_EnA
PD4: CN6.25 U4.85(PD4) ; port MC1_EnB
PD5: CN6.28 U4.86(PD5) ; port JOY_DOWN
PD6: CN6.27 U4.87(PD6) ; port JOY_RIGHT
PD7: CN6.29 R57.2 R58.2 U4.88(PD7)
PD8: CN7.12 U4.55(PD8) ; port MC1_MC2_PFC_Ind  [project net MC1_MC2_PFC_Ind]
PD9: CN7.7 U4.56(PD9) ; port MC1_MC2_PFC_Vac  [project net MC1_MC2_PFC_Vac]
PD10: CN7.8 U4.57(PD10) ; port MC2_Cin+_ADC34
PD11: CN7.5 U4.58(PD11) ; port MC2_Ain+_ADC34
PD12: R39.2 R40.2 U4.59(PD12)
PD13: R41.2 R42.2 U4.60(PD13)
PD14: CN7.3 R45.2 R46.2 U4.61(PD14)
PD15: R43.2 R44.2 U4.62(PD15)
PE0: CN6.37 U4.97(PE0) ; port LCD_CS
PE1: CN6.40 U4.98(PE1) ; port USART1_RX
PE2: CN6.42 R1.2 R2.2 U4.1(PE2)
PE3: CN6.41 R3.2 R4.2 U4.2(PE3)
PE4: CN6.44 R5.2 R6.2 U4.3(PE4)
PE5: CN6.43 R7.2 R8.2 U4.4(PE5)
PE6: CN6.46 R111.2 U4.5(PE6-WKUP3) ; port TRACE_D3
PE7: CN7.29 U4.38(PE7) ; port JOY_UP
PE8: CN7.28 R23.2 R24.2 U4.39(PE8)
PE9: CN7.27 R25.2 R26.2 U4.40(PE9)
PE10: CN7.25 R27.2 R28.2 U4.41(PE10)
PE11: CN7.22 R29.2 R30.2 U4.42(PE11)
PE12: CN7.21 U4.43(PE12) ; port MC1_PWM_3L
PE13: CN7.20 R31.2 R32.2 U4.44(PE13)
PE14: CN7.18 U4.45(PE14) ; port ACP_RESET, port SPI2_DIR
PE15: CN7.17 R33.2 R34.2 U4.46(PE15)
PF0: C51.1 SB14.1 U4.12(PF0-OSC_IN) X2.2
PF1: R205.1 SB15.1 U4.13(PF1-OSC_OUT)
PF2: CN7.46 R11.1 U4.19(PF2)
PF4: CN7.41 U4.27(PF4) ; port MC1_HeatsinkTemp
PF6: CN6.14 U4.73(PF6) ; port I2C2_SCL
PF9: CN6.45 U4.10(PF9) ; port SPI2_SCK
PF10: CN6.47 U4.11(PF10) ; port MC2_DissipativeBrake
RESET#: B1.2(B0) B1.3(B1) C116.2 D1.1(A) R206.2 U4.14(NRST) ; port RESET#
NetC2_2: R33.1 ; port MC1_STOP
NetC3_1: R9.2 ; port MC1_BusVoltage
NetC13_2: R57.1 ; port MC1_EnIndex
NetC14_1: R13.1 ; port MC2_BusVoltage
NetC19_2: R11.2 ; port MC2_HeatsinkTemp
NetC21_1: R37.2 ; port OPAMP4_OUT
NetC27_2: R41.1 ; port MC2_EnB
NetC28_2: R17.2 ; port MC2_EnIndex
NetC29_2: R21.2 ; port OPAMP3_IN-
NetC45_1: C45.1 R196.1 X1.1
NetC46_1: C46.1 R205.2 X2.1
NetC50_1: C50.1 R197.1 X1.4
NetC52_2: R40.1 ; port TS_CT
NetC68_1: R46.1 ; port LED_FB
NetC133_1: R45.1 ; port OPAMP2_IN2+
NetC134_1: R35.2 ; port OPAMP4_IN1+
NetC136_1: R19.2 ; port OPAMP3_IN+
NetCN2_3: R25.1 ; port MC1_PWM_1H
NetCN2_5: R23.1 ; port MC1_PWM_1L
NetCN2_7: R29.1 ; port MC1_PWM_2H
NetCN2_9: R27.1 ; port MC1_PWM_2L
NetCN2_11: R31.1 ; port MC1_PWM_3H
NetCN2_21: R5.1 ; port MC1_ICL_SHUTOUT
NetCN2_23: R7.1 ; port MC1_DissipativeBrake
NetCN4_3: R47.1 ; port MC2_PWM_1H
NetCN4_5: R51.1 ; port MC2_PWM_1L
NetCN4_9: R53.1 ; port MC2_PWM_2L
NetCN4_11: R49.1 ; port MC2_PWM_3H
NetCN4_13: R55.1 ; port MC2_PWM_3L
NetCN4_21: R43.1 ; port MC2_ICL_SHUTOUT
NetCN6_11: CN6.11 SB12.2
NetCN6_15: CN6.15 SB13.2
NetCN6_51: CN6.51 ; port DB_PB11
NetCN6_52: CN6.52 ; port DB_PB12
NetCN7_2: CN7.2 ; port DB_PD15
NetCN7_4: CN7.4 ; port DB_PD13
NetCN7_6: CN7.6 ; port DB_PD12
NetCN7_9: CN7.9 R187.2
NetCN7_11: CN7.11 R206.1
NetCN7_23: CN7.23 SB14.2
NetCN7_26: CN7.26 SB15.2
NetCN9_12: R2.1 ; port TRACE_CK
NetCN9_18: R8.1 ; port TRACE_D2
NetCN16_2: R34.1 ; port MicroSD_CS
NetCN16_10: R48.1 ; port SDcard_detect
NetD1_2: D1.2(K) JP10.1(COMMON)
NetD2_1: D2.1(A) ; port Bootloader_BOOT0
NetD2_2: D2.2(K) JP9.1(COMMON)
NetJP1_2: JP1.2(NO) ; port I2C2_SMB
NetJP10_2: JP10.2(NO) ; port Bootloader_RESET
NetJP18_1: JP18.1 ; port I2S_MCK
NetJP18_3: JP18.3 ; port IR_IN
NetJP19_2: R20.2 ; port Hum_In
NetPG3SA_2: R15.2 ; port MC_DAC_OUT1
NetR4_1: R4.1 ; port TRACE_D0
NetR6_1: R6.1 ; port TRACE_D1
NetR10_2: R10.2 ; port LDR_OUT
NetR14_1: R14.1 ; port COM_IN+
NetR16_2: R16.2 ; port I2S_WS
NetR18_2: R18.2 ; port USB_disconnect
NetR24_1: R24.1 ; port LED1
NetR26_1: R26.1 ; port LED2
NetR28_1: R28.1 ; port LED3
NetR30_1: R30.1 ; port LED4
NetR32_1: R32.1 ; port LED_DRV
NetR36_2: R36.2 ; port SHIELD_CT
NetR38_2: R38.2 ; port SHIELD
NetR39_1: R39.1 ; port MC2_Bin+_ADC34
NetR42_1: R42.1 ; port TS1
NetR44_1: R44.1 ; port TS2
NetR50_1: R50.1 ; port Hum_Out
NetR52_1: R52.1 ; port I2S_SCK
NetR54_1: R54.1 ; port I2S_DOUT
NetR56_1: R56.1 ; port I2S_DIN
NetR58_1: R58.1 ; port E2P_CS
NetR111_1: R111.1 ; port Key_Button
NetR129_1: R129.1 ; port RS485_DIR
NetR166_2: R166.2 SW1.2

Not connected (* = marked no-connect by the designer): CN7 52; X1 2 3

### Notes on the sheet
- PA0
- (near CN6) Extension connector
- (near CN6) Left
- PA4
- PC11
- PC12
- PA8
- PA9
- PC8
- PC10
- (near SB13) Open by default
- PC1
- PC6
- PB0
- PB2
- PD13
- PD14
- PD15
- PB8
- PD12
- PD7
- PB11
- PB12
- PE15
- (near CN7) Right
- PE14
- PE13
- PE9
- PE10
- PE11
- PF2
- PE8
- PE6
- PE3
- PE4
- PE5
- PE2
- STM32303C-EVAL MCU
- MB1019
- 2
- 13

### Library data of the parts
B1 = SW PUSHBUTTON: SE PUSHBUTTON
C45 C46 C50 C51 = CAP: Capacitor
C116 = CAP: Capacitor; Value: 100pF
CN6 CN7 = Header 26X2_1: Header, 26-Pin, Dual row
D1 D2 = Diode: Default Diode; Code - JEDEC: DO-214-AB
JP1 JP9 JP10 = JP2
JP18 = Jumper3
R1-R11 R13-R21 R23-R58 R111 R129 R187 R196 R197 R205 R206 = Res1: Resistor; Value: 1K
R166 = res1: Resistor; Value: 1K
SB12-SB15 = Circuit Breaker
SW1 = SW-SPDT: SPDT Subminiature Toggle Switch, Right Angle Mounting, Vertical Actuation; Revision 1: Jul-2002: Re-released for DXP Platform.; Revision 2: 17-Dec-2003: Schematic revised, PCB Footprint replaced.
X1 = MC306
X2 = CRYSTAL

## Sheet MotorCtrl.SchDoc
size A3; Revision: C.1
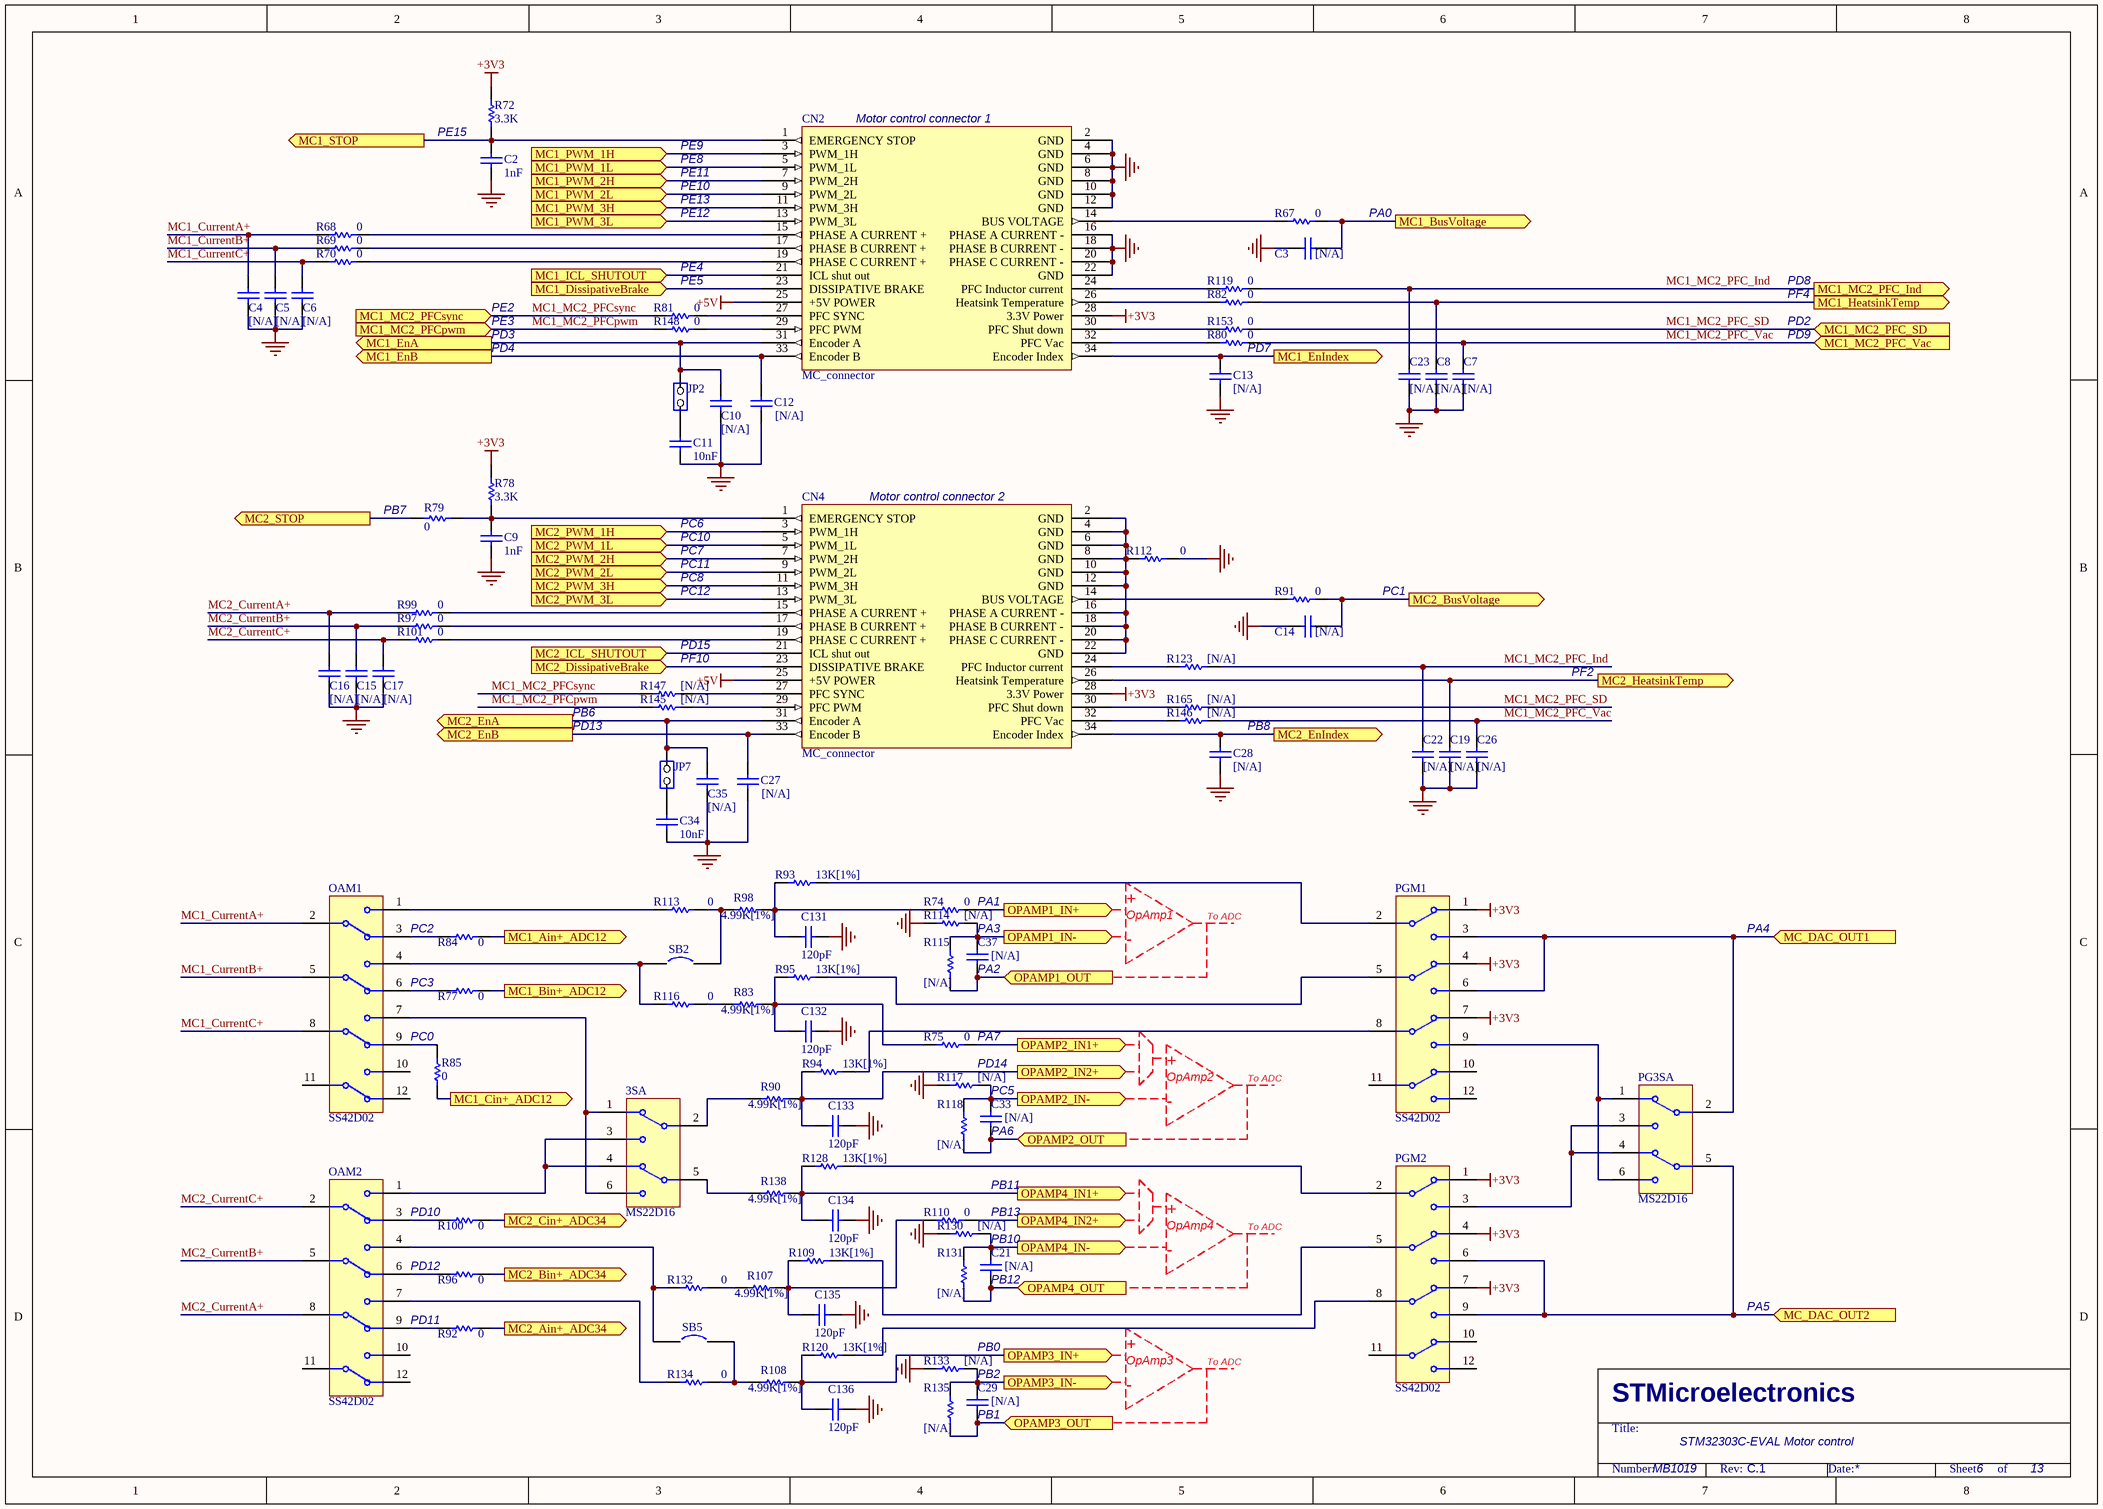
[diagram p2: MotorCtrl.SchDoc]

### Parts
3SA  MS22D16  [MS22D16]
C2  1nF  [0603C]
C3  [N/A]  [0603C]
C4  [N/A]  [0603C]
C5  [N/A]  [0603C]
C6  [N/A]  [0603C]
C7  [N/A]  [0603C]
C8  [N/A]  [0603C]
C9  1nF  [0603C]
C10  [N/A]  [0603C]
C11  10nF  [0603C]
C12  [N/A]  [0603C]
C13  [N/A]  [0603C]
C14  [N/A]  [0603C]
C15  [N/A]  [0603C]
C16  [N/A]  [0603C]
C17  [N/A]  [0603C]
C19  [N/A]  [0603C]
C21  [N/A]  [0603C]
C22  [N/A]  [0603C]
C23  [N/A]  [0603C]
C26  [N/A]  [0603C]
C27  [N/A]  [0603C]
C28  [N/A]  [0603C]
C29  [N/A]  [0603C]
C33  [N/A]  [0603C]
C34  10nF  [0603C]
C35  [N/A]  [0603C]
C37  [N/A]  [0603C]
C131  120pF  [0603C]
C132  120pF  [0603C]
C133  120pF  [0603C]
C134  120pF  [0603C]
C135  120pF  [0603C]
C136  120pF  [0603C]
CN2  MC_connector  [IDC34S]
CN4  MC_connector  [IDC34S]
JP2  (no value)  [SIP2]
JP7  (no value)  [SIP2]
OAM1  SS42D02  [SS42D02]
OAM2  SS42D02  [SS42D02]
PG3SA  MS22D16  [MS22D16]
PGM1  SS42D02  [SS42D02]
PGM2  SS42D02  [SS42D02]
R67  0  [0603R]
R68  0  [0603R]
R69  0  [0603R]
R70  0  [0603R]
R72  3.3K  [0603R]
R74  0  [0603R]
R75  0  [0603R]
R77  0  [0603R]
R78  3.3K  [0603R]
R79  0  [0603R]
R80  0  [0603R]
R81  0  [0603R]
R82  0  [0603R]
R83  4.99K[1%]  [0603R]
R84  0  [0603R]
R85  0  [0603R]
R90  4.99K[1%]  [0603R]
R91  0  [0603R]
R92  0  [0603R]
R93  13K[1%]  [0603R]
R94  13K[1%]  [0603R]
R95  13K[1%]  [0603R]
R96  0  [0603R]
R97  0  [0603R]
R98  4.99K[1%]  [0603R]
R99  0  [0603R]
R100  0  [0603R]
R101  0  [0603R]
R107  4.99K[1%]  [0603R]
R108  4.99K[1%]  [0603R]
R109  13K[1%]  [0603R]
R110  0  [0603R]
R112  0  [0603R]
R113  0  [0603R]
R114  [N/A]  [0603R]
R115  [N/A]  [0603R]
R116  0  [0603R]
R117  [N/A]  [0603R]
R118  [N/A]  [0603R]
R119  0  [0603R]
R120  13K[1%]  [0603R]
R123  [N/A]  [0603R]
R128  13K[1%]  [0603R]
R130  [N/A]  [0603R]
R131  [N/A]  [0603R]
R132  0  [0603R]
R133  [N/A]  [0603R]
R134  0  [0603R]
R135  [N/A]  [0603R]
R138  4.99K[1%]  [0603R]
R145  [N/A]  [0603R]
R146  [N/A]  [0603R]
R147  [N/A]  [0603R]
R148  0  [0603R]
R153  0  [0603R]
R165  [N/A]  [0603R]
SB2  (no value)  [JP2_SMD]
SB5  (no value)  [JP2_SMD]

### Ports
MC1_Ain+_ADC12 (out), MC1_Bin+_ADC12 (out), MC1_BusVoltage (out), MC1_Cin+_ADC12 (out), MC1_DissipativeBrake (in), MC1_EnA (out), MC1_EnB (out), MC1_EnIndex (out), MC1_HeatsinkTemp (out), MC1_ICL_SHUTOUT (in), MC1_MC2_PFC_Ind (out), MC1_MC2_PFC_SD (in), MC1_MC2_PFC_Vac (in), MC1_MC2_PFCpwm (in), MC1_MC2_PFCsync (in), MC1_PWM_1H (in), MC1_PWM_1L (in), MC1_PWM_2H (in), MC1_PWM_2L (in), MC1_PWM_3H (in), MC1_PWM_3L (in), MC1_STOP (out), MC2_Ain+_ADC34 (out), MC2_Bin+_ADC34 (out), MC2_BusVoltage (out), MC2_Cin+_ADC34 (out), MC2_DissipativeBrake (in), MC2_EnA (out), MC2_EnB (out), MC2_EnIndex (out), MC2_HeatsinkTemp (out), MC2_ICL_SHUTOUT (in), MC2_PWM_1H (in), MC2_PWM_1L (in), MC2_PWM_2H (in), MC2_PWM_2L (in), MC2_PWM_3H (in), MC2_PWM_3L (in), MC2_STOP (out), MC_DAC_OUT1 (in), MC_DAC_OUT2 (in), OPAMP1_IN+ (out), OPAMP1_IN- (out), OPAMP1_OUT (in), OPAMP2_IN1+ (out), OPAMP2_IN2+ (out), OPAMP2_IN- (out), OPAMP2_OUT (in), OPAMP3_IN+ (out), OPAMP3_IN- (out), OPAMP3_OUT (in), OPAMP4_IN1+ (out), OPAMP4_IN2+ (out), OPAMP4_IN- (out), OPAMP4_OUT (in)

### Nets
+3V3: CN2.28(3.3V_Power) CN4.28(3.3V_Power) PGM1.1 PGM1.4 PGM1.7 PGM2.1 PGM2.4 PGM2.7 R72.2 R78.2
+5V: CN2.25(+5V_POWER) CN4.25(+5V_POWER)
GND: C2.1 C3.2 C4.1 C5.1 C6.1 C7.1 C8.1 C9.1 C10.1 C11.1 C12.1 C13.1 C14.2 C15.1 C16.1 C17.1 C19.1 C22.1 C23.1 C26.1 C27.1 C28.1 C34.1 C35.1 C131.2 C132.2 C133.2 C134.2 C135.2 C136.2 CN2.2(GND) CN2.4(GND) CN2.6(GND) CN2.8(GND) CN2.10(GND) CN2.12(GND) CN2.16(PHASE_A_CURRENT_-) CN2.18(PHASE_B_CURRENT_-) CN2.20(PHASE_C_CURRENT_-) CN2.22(GND) R112.1 R114.1 R117.1 R130.1 R133.1
MC1_CurrentA+: C4.2 OAM1.2 R68.2
MC1_CurrentB+: C5.2 OAM1.5 R69.2
MC1_CurrentC+: C6.2 OAM1.8 R70.2
MC1_MC2_PFC_Ind: C22.2 C23.2 R119.1 R123.1 ; port MC1_MC2_PFC_Ind
MC1_MC2_PFC_SD: R153.1 R165.1 ; port MC1_MC2_PFC_SD
MC1_MC2_PFC_Vac: C7.2 C26.2 R80.1 R146.1 ; port MC1_MC2_PFC_Vac
MC1_MC2_PFCpwm: R145.2 R148.2 ; port MC1_MC2_PFCpwm
MC1_MC2_PFCsync: R81.2 R147.2 ; port MC1_MC2_PFCsync
MC2_CurrentA+: C16.2 OAM2.8 R99.2
MC2_CurrentB+: C15.2 OAM2.5 R97.2
MC2_CurrentC+: C17.2 OAM2.2 R101.2
PA1: R74.1 ; port OPAMP1_IN+
PA2: C37.1 R115.1 ; port OPAMP1_OUT
PA3: C37.2 R114.2 R115.2 ; port OPAMP1_IN-
PA5: PG3SA.5 PGM2.6 PGM2.9 ; port MC_DAC_OUT2
PA6: C33.1 R118.1 ; port OPAMP2_OUT
PA7: R75.1 ; port OPAMP2_IN1+
PB1: C29.1 R135.1 ; port OPAMP3_OUT
PB6: C35.2 CN4.31(Encoder_A) JP7.1(COMMON) ; port MC2_EnA
PB7: R79.2 ; port MC2_STOP
PB10: C21.2 R130.2 R131.2 ; port OPAMP4_IN-
PB13: R110.1 ; port OPAMP4_IN2+
PC0: R85.2 ; port MC1_Cin+_ADC12
PC2: R84.1 ; port MC1_Ain+_ADC12
PC3: R77.1 ; port MC1_Bin+_ADC12
PC5: C33.2 R117.2 R118.2 ; port OPAMP2_IN-
PC7: CN4.7(PWM_2H) ; port MC2_PWM_2H
PD3: C10.2 CN2.31(Encoder_A) JP2.1(COMMON) ; port MC1_EnA
PD4: C12.2 CN2.33(Encoder_B) ; port MC1_EnB
PD10: R100.1 ; port MC2_Cin+_ADC34
PD11: R92.1 ; port MC2_Ain+_ADC34
PE12: CN2.13(PWM_3L) ; port MC1_PWM_3L
PF4: C8.2 R82.2 ; port MC1_HeatsinkTemp
PF10: CN4.23(DISSIPATIVE_BRAKE) ; port MC2_DissipativeBrake
Net3SA_1: 3SA.1 3SA.6 OAM1.7
Net3SA_2: 3SA.2 R90.1
Net3SA_3: 3SA.3 3SA.4 OAM2.1
Net3SA_5: 3SA.5 R138.1
NetC2_2: C2.2 CN2.1(EMERGENCY_STOP) R72.1 ; port MC1_STOP
NetC3_1: C3.1 R67.1 ; port MC1_BusVoltage
NetC9_2: C9.2 CN4.1(EMERGENCY_STOP) R78.1 R79.1
NetC11_2: C11.2 JP2.2(NO)
NetC13_2: C13.2 CN2.34(Encoder_Index) ; port MC1_EnIndex
NetC14_1: C14.1 R91.1 ; port MC2_BusVoltage
NetC19_2: C19.2 CN4.26(Heatsink_Temperature) ; port MC2_HeatsinkTemp
NetC21_1: C21.1 R131.1 ; port OPAMP4_OUT
NetC27_2: C27.2 CN4.33(Encoder_B) ; port MC2_EnB
NetC28_2: C28.2 CN4.34(Encoder_Index) ; port MC2_EnIndex
NetC29_2: C29.2 R133.2 R135.2 ; port OPAMP3_IN-
NetC34_2: C34.2 JP7.2(NO)
NetC131_1: C131.1 R74.2 R93.1 R98.2
NetC132_1: C132.1 R75.2 R83.2 R95.1
NetC133_1: C133.1 R90.2 R94.1 ; port OPAMP2_IN2+
NetC134_1: C134.1 R128.1 R138.2 ; port OPAMP4_IN1+
NetC135_1: C135.1 R107.2 R109.1 R110.2
NetC136_1: C136.1 R108.2 R120.1 ; port OPAMP3_IN+
NetCN2_3: CN2.3(PWM_1H) ; port MC1_PWM_1H
NetCN2_5: CN2.5(PWM_1L) ; port MC1_PWM_1L
NetCN2_7: CN2.7(PWM_2H) ; port MC1_PWM_2H
NetCN2_9: CN2.9(PWM_2L) ; port MC1_PWM_2L
NetCN2_11: CN2.11(PWM_3H) ; port MC1_PWM_3H
NetCN2_14: CN2.14(BUS_VOLTAGE) R67.2
NetCN2_15: CN2.15(PHASE_A_CURRENT_+) R68.1
NetCN2_17: CN2.17(PHASE_B_CURRENT_+) R69.1
NetCN2_19: CN2.19(PHASE_C_CURRENT_+) R70.1
NetCN2_21: CN2.21(ICL_shut_out) ; port MC1_ICL_SHUTOUT
NetCN2_23: CN2.23(DISSIPATIVE_BRAKE) ; port MC1_DissipativeBrake
NetCN2_24: CN2.24(PFC_Inductor_current) R119.2
NetCN2_26: CN2.26(Heatsink_Temperature) R82.1
NetCN2_27: CN2.27(PFC_SYNC) R81.1
NetCN2_29: CN2.29(PFC_PWM) R148.1
NetCN2_30: CN2.30(PFC_Shut_down) R153.2
NetCN2_32: CN2.32(PFC_Vac) R80.2
NetCN4_2: CN4.2(GND) CN4.4(GND) CN4.6(GND) CN4.8(GND) CN4.10(GND) CN4.12(GND) CN4.16(PHASE_A_CURRENT_-) CN4.18(PHASE_B_CURRENT_-) CN4.20(PHASE_C_CURRENT_-) CN4.22(GND) R112.2
NetCN4_3: CN4.3(PWM_1H) ; port MC2_PWM_1H
NetCN4_5: CN4.5(PWM_1L) ; port MC2_PWM_1L
NetCN4_9: CN4.9(PWM_2L) ; port MC2_PWM_2L
NetCN4_11: CN4.11(PWM_3H) ; port MC2_PWM_3H
NetCN4_13: CN4.13(PWM_3L) ; port MC2_PWM_3L
NetCN4_14: CN4.14(BUS_VOLTAGE) R91.2
NetCN4_15: CN4.15(PHASE_A_CURRENT_+) R99.1
NetCN4_17: CN4.17(PHASE_B_CURRENT_+) R97.1
NetCN4_19: CN4.19(PHASE_C_CURRENT_+) R101.1
NetCN4_21: CN4.21(ICL_shut_out) ; port MC2_ICL_SHUTOUT
NetCN4_24: CN4.24(PFC_Inductor_current) R123.2
NetCN4_27: CN4.27(PFC_SYNC) R147.1
NetCN4_29: CN4.29(PFC_PWM) R145.1
NetCN4_30: CN4.30(PFC_Shut_down) R165.2
NetCN4_32: CN4.32(PFC_Vac) R146.2
NetOAM1_1: OAM1.1 R113.2
NetOAM1_3: OAM1.3 R84.2
NetOAM1_4: OAM1.4 R116.2 SB2.1
NetOAM1_6: OAM1.6 R77.2
NetOAM1_9: OAM1.9 R85.1
NetOAM2_3: OAM2.3 R100.2
NetOAM2_4: OAM2.4 R132.2 SB5.1
NetOAM2_6: OAM2.6 R96.2
NetOAM2_7: OAM2.7 R134.2
NetOAM2_9: OAM2.9 R92.2
NetPG3SA_1: PG3SA.1 PG3SA.6 PGM1.9
NetPG3SA_2: PG3SA.2 PGM1.3 PGM1.6 ; port MC_DAC_OUT1
NetPG3SA_3: PG3SA.3 PG3SA.4 PGM2.3
NetPGM1_2: PGM1.2 R93.2
NetPGM1_5: PGM1.5 R95.2
NetPGM1_8: PGM1.8 R94.2
NetPGM2_2: PGM2.2 R128.2
NetPGM2_5: PGM2.5 R109.2
NetPGM2_8: PGM2.8 R120.2
NetR39_1: R96.1 ; port MC2_Bin+_ADC34
NetR83_1: R83.1 R116.1
NetR98_1: R98.1 R113.1 SB2.2
NetR107_1: R107.1 R132.1
NetR108_1: R108.1 R134.1 SB5.2

Not connected (* = marked no-connect by the designer): OAM1 10 11 12; OAM2 10 11 12; PGM1 10 11 12; PGM2 10 11 12

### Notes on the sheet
- PE15
- PE9
- PE8
- PE11
- (near CN2) Motor control connector 1
- PE10
- PE13
- PE12
- PA0
- PE2
- PE5
- PE4
- PF4
- PD8
- PD3
- PD4
- PE3
- (near R80) PD7
- PD2
- PD9
- (near R79) PB7
- (near CN4) Motor control connector 2
- PC6
- PC10
- PC7
- PC11
- PC8
- PC12
- PD15
- PC1
- PB6
- PF10
- PF2
- PD13
- PB8
- PA1
- +
- OpAmp1
- To ADC
- PC2
- PC3
- PA3
- (near C37) PA2
- -
- PA4
- PC0
- (near R75) PA7
- PD14
- PC5
- OpAmp2
- (near C33) PA6
- PB11
- PD10
- PB13
- PB10
- OpAmp4
- PD12
- PD11
- (near C21) PB12
- PA5
- (near R133) PB0
- PB2
- OpAmp3
- (near C29) PB1
- STM32303C-EVAL Motor control
- MB1019
- 6
- 13

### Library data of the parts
3SA PG3SA = MS22D16: DPDT; Revision 1: Jul-2002: Re-released for DXP Platform.; Revision 2: 17-Dec-2003: Schematic revised, PCB Footprint replaced.
C2 C9 = CAP: Capacitor; Value: 100pF
C3-C8 C10-C17 C19 C21-C23 C26-C29 C33-C35 C37 C131-C136 = cap: Capacitor; Value: 100pF
CN2 CN4 = MC_connector_1
JP2 JP7 = JP2
OAM1 OAM2 = SS42D02_1: SPDT Subminiature Toggle Switch, Right Angle Mounting, Vertical Actuation; Revision 1: Jul-2002: Re-released for DXP Platform.; Revision 2: 17-Dec-2003: Schematic revised, PCB Footprint replaced.
PGM1 PGM2 = SS42D02: SPDT Subminiature Toggle Switch, Right Angle Mounting, Vertical Actuation; Revision 1: Jul-2002: Re-released for DXP Platform.; Revision 2: 17-Dec-2003: Schematic revised, PCB Footprint replaced.
R67-R70 R72 R74 R75 R77-R85 R90-R101 R107-R110 R112-R120 R123 R128 R130-R135 R138 R145-R148 R153 R165 = Res1: Resistor; Value: 1K
SB2 SB5 = Circuit Breaker

## Sheet RS232_RS485_IrDA.SchDoc
size A4; Revision: C.1
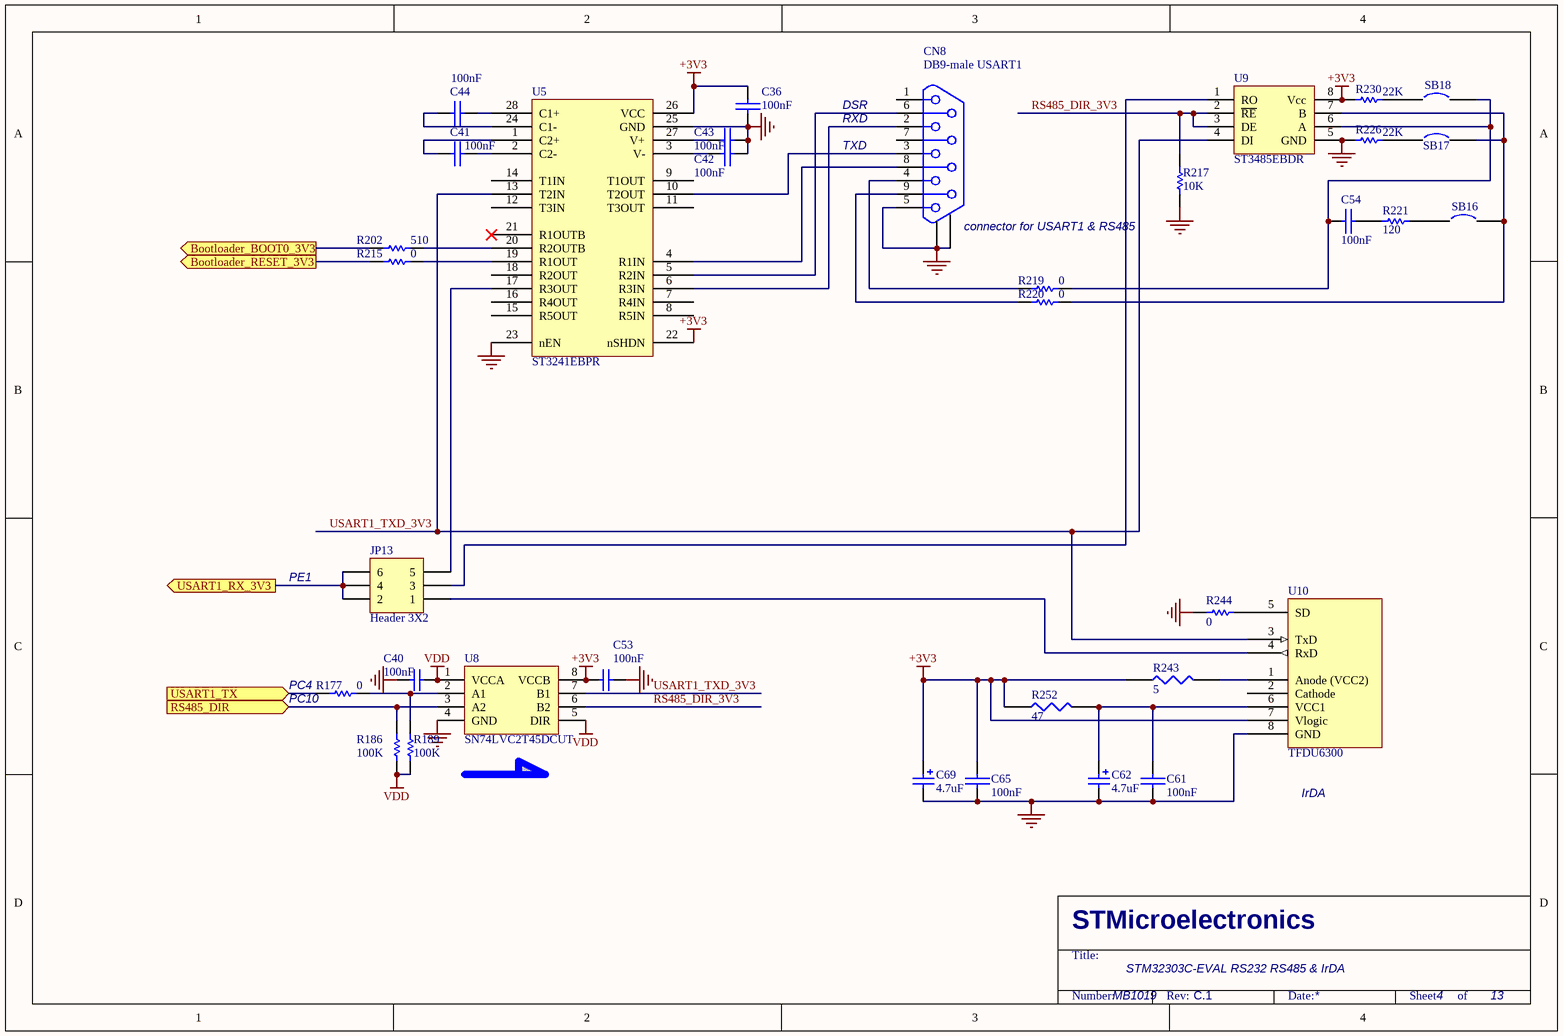
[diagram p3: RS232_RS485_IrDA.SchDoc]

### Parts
C36  100nF  [0603C]
C40  100nF  [0603C]
C41  100nF  [0603C]
C42  100nF  [0603C]
C43  100nF  [0603C]
C44  100nF  [0603C]
C53  100nF  [0603C]
C54  100nF  [0603C]
C61  100nF  [0603C]
C62  4.7uF  [TAN-A]
C65  100nF  [0603C]
C69  4.7uF  [TAN-A]
CN8  DB9-male USART1  [DB9/M]
JP13  Header 3X2  [2*3P]
R177  0  [0603R]
R186  100K  [0603R]
R189  100K  [0603R]
R202  510  [0603R]
R215  0  [0603R]
R217  10K  [0603R]
R219  0  [0603R]
R220  0  [0603R]
R221  120  [0603R]
R226  22K  [0603R]
R230  22K  [0603R]
R243  5  [0603R]
R244  0  [0603R]
R252  47  [0603R]
SB16  (no value)  [JP2_SMD]
SB17  (no value)  [JP2_SMD]
SB18  (no value)  [JP2_SMD]
U5  ST3241EBPR  [SSOP28]
U8  SN74LVC2T45DCUT  [VSSOP8]
U9  ST3485EBDR  [SO8]
U10  TFDU6300  [IR_VISHAY3]

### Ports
Bootloader_BOOT0_3V3 (out), Bootloader_RESET_3V3 (out), RS485_DIR (in), USART1_RX_3V3 (out), USART1_TX (in)

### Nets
+3V3: C36.2 C53.2 C65.1 C69.1 R230.2 R243.1 R252.1 U5.22(nSHDN) U5.26(VCC) U8.8(VCCB) U9.8(Vcc) U10.7(Vlogic)
GND: C36.1 C40.1 C42.2 C43.2 C53.1 C61.2 C62.2 C65.2 C69.2 CN8.0 CN8.5 R217.1 R226.2 R244.2 U5.23(nEN) U5.25(GND) U8.4(GND) U9.5(GND) U10.8(GND)
VDD: C40.2 R186.2 R189.2 U8.1(VCCA) U8.5(DIR)
PC4: R177.2 ; port USART1_TX
PE1: JP13.2 JP13.4 JP13.6 ; port USART1_RX_3V3
RS485_DIR_3V3: R217.2 U8.6(B2) U9.2(~{RE}) U9.3(DE)
USART1_TXD_3V3: U5.13(T2IN) U8.7(B1) U9.4(DI) U10.3(TxD)
NetC41_1: C41.1 U5.1(C2+)
NetC41_2: C41.2 U5.2(C2-)
NetC42_1: C42.1 U5.3(V-)
NetC43_1: C43.1 U5.27(V+)
NetC44_1: C44.1 U5.24(C1-)
NetC44_2: C44.2 U5.28(C1+)
NetC54_1: C54.1 R221.1
NetC54_2: C54.2 R219.1 SB18.2 U9.6(A)
NetC61_1: C61.1 C62.1 R252.2 U10.6(VCC1)
NetCN8_2: CN8.2 U5.6(R3IN)
NetCN8_3: CN8.3 U5.10(T2OUT)
NetCN8_4: CN8.4 R219.2
NetCN8_6: CN8.6 U5.5(R2IN)
NetCN8_8: CN8.8 U5.4(R1IN)
NetCN8_9: CN8.9 R220.2
NetD2_1: R202.1 ; port Bootloader_BOOT0_3V3
NetJP10_2: R215.1 ; port Bootloader_RESET_3V3
NetJP13_1: JP13.1 U10.4(RxD)
NetJP13_3: JP13.3 U9.1(RO)
NetJP13_5: JP13.5 U5.17(R3OUT)
NetR129_1: R186.1 U8.3(A2) ; port RS485_DIR
NetR177_1: R177.1 R189.1 U8.2(A1)
NetR202_2: R202.2 U5.20(R2OUTB)
NetR215_2: R215.2 U5.19(R1OUT)
NetR220_1: R220.1 SB16.2 SB17.2 U9.7(B)
NetR221_2: R221.2 SB16.1
NetR226_1: R226.1 SB17.1
NetR230_1: R230.1 SB18.1
NetR243_2: R243.2 U10.1(Anode_(VCC2))
NetR244_1: R244.1 U10.5(SD)

Not connected (* = marked no-connect by the designer): CN8 1 7; U5 7(R4IN) 8(R5IN) 9(T1OUT) 11(T3OUT) 12(T3IN) 14(T1IN) 15(R5OUT) 16(R4OUT) 18(R2OUT) 21(R1OUTB)*; U10 2(Cathode)

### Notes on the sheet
- DSR
- RXD
- TXD
- (near CN8) connector for USART1 & RS485
- PE1
- (near R177) PC4
- (near R177) PC10
- IrDA
- STM32303C-EVAL RS232 RS485 & IrDA
- MB1019
- 4
- 13

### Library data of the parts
C36 C41-C44 C54 C61 C65 = CAP: Capacitor
C40 C53 = CAP: Capacitor; Value: 100pF
C62 C69 = Cap Pol1: Polarized Capacitor (Radial); Value: 100pF
CN8 = DB9
JP13 = Header 3X2: Header, 3-Pin, Dual row
R177 = res1: Resistor; Value: 1K
R186 R189 R202 R215 R217 R219-R221 R226 R230 R244 = Res1: Resistor; Value: 1K
R243 R252 = RES1
SB16-SB18 = Circuit Breaker
U5 = ST3241
U9 = ST485ABDR
U10 = TFDU4300

## Sheet Touch Sensing.SchDoc
size A4; Revision: C.1
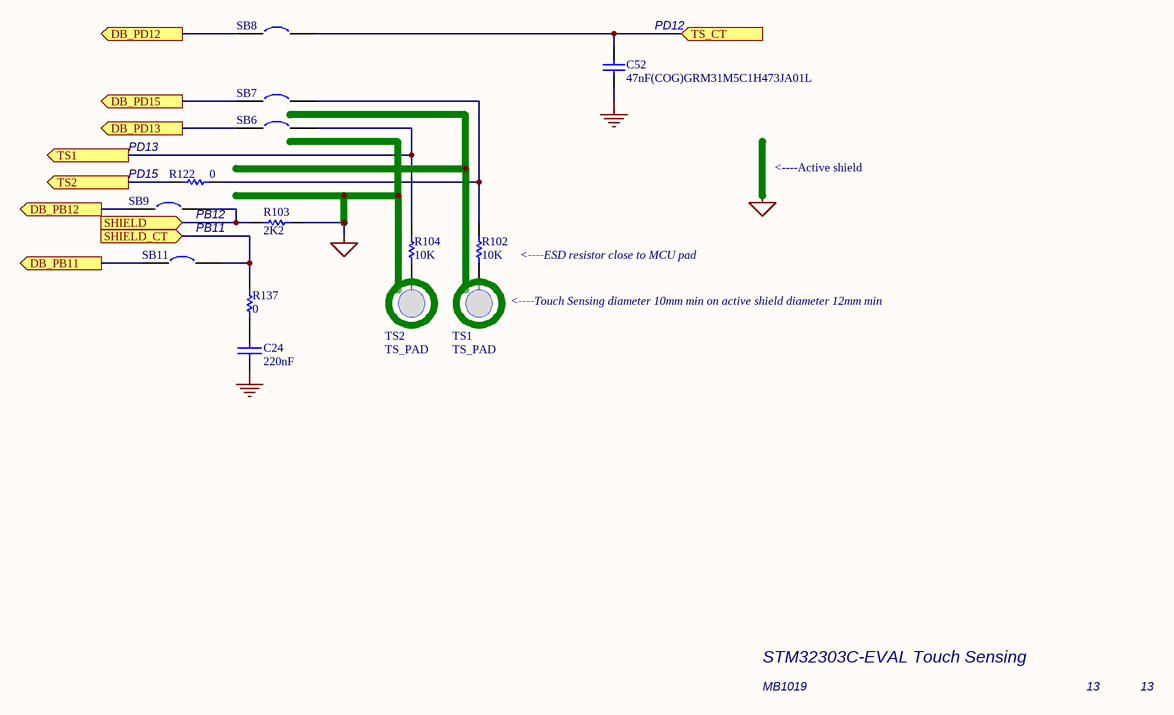
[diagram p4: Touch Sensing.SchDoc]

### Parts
C24  220nF  [0603C]
C52  47nF(COG)GRM31M5C1H473JA01L  [1206C]
R102  10K  [0603R]
R103  2K2  [0603R]
R104  10K  [0603R]
R122  0  [0603R]
R137  0  [0603R]
SB6  (no value)  [JP2_SMD]
SB7  (no value)  [JP2_SMD]
SB8  (no value)  [JP2_SMD]
SB9  (no value)  [JP2_SMD]
SB11  (no value)  [JP2_SMD]
TS1  TS_PAD  [TS_PAD]
TS2  TS_PAD  [TS_PAD]

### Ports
DB_PB11 (out), DB_PB12 (out), DB_PD12 (out), DB_PD13 (out), DB_PD15 (out), SHIELD (in), SHIELD_CT (in), TS1 (out), TS2 (out), TS_CT (in)

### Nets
GND: C24.1 C52.1
TS_SHIELD: R103.2
NetC24_2: C24.2 R137.2
NetC52_2: C52.2 SB8.2 ; port TS_CT
NetCN6_51: SB11.1 ; port DB_PB11
NetCN6_52: SB9.1 ; port DB_PB12
NetCN7_2: SB7.1 ; port DB_PD15
NetCN7_4: SB6.1 ; port DB_PD13
NetCN7_6: SB8.1 ; port DB_PD12
NetR36_2: R137.1 SB11.2 ; port SHIELD_CT
NetR38_2: R103.1 SB9.2 ; port SHIELD
NetR42_1: R104.1 SB6.2 ; port TS1
NetR44_1: R122.2 ; port TS2
NetR102_1: R102.1 R122.1 SB7.2
NetR102_2: R102.2 TS1.1
NetR104_2: R104.2 TS2.1

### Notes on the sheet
- (near C52) PD12
- PD13
- PD15
- <----Active shield
- (near SB9) PB12
- PB11
- <----ESD resistor close to MCU pad
- <----Touch Sensing diameter 10mm min on active shield diameter 12mm min
- STM32303C-EVAL Touch Sensing
- MB1019
- 13

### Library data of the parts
C24 = CAP: Capacitor
C52 = CAP: Capacitor; Value: 100pF
R102-R104 R122 R137 = Res1: Resistor; Value: 1K
SB6-SB9 SB11 = Circuit Breaker

## Sheet Peripherals.SchDoc
size A4; Revision: C.1
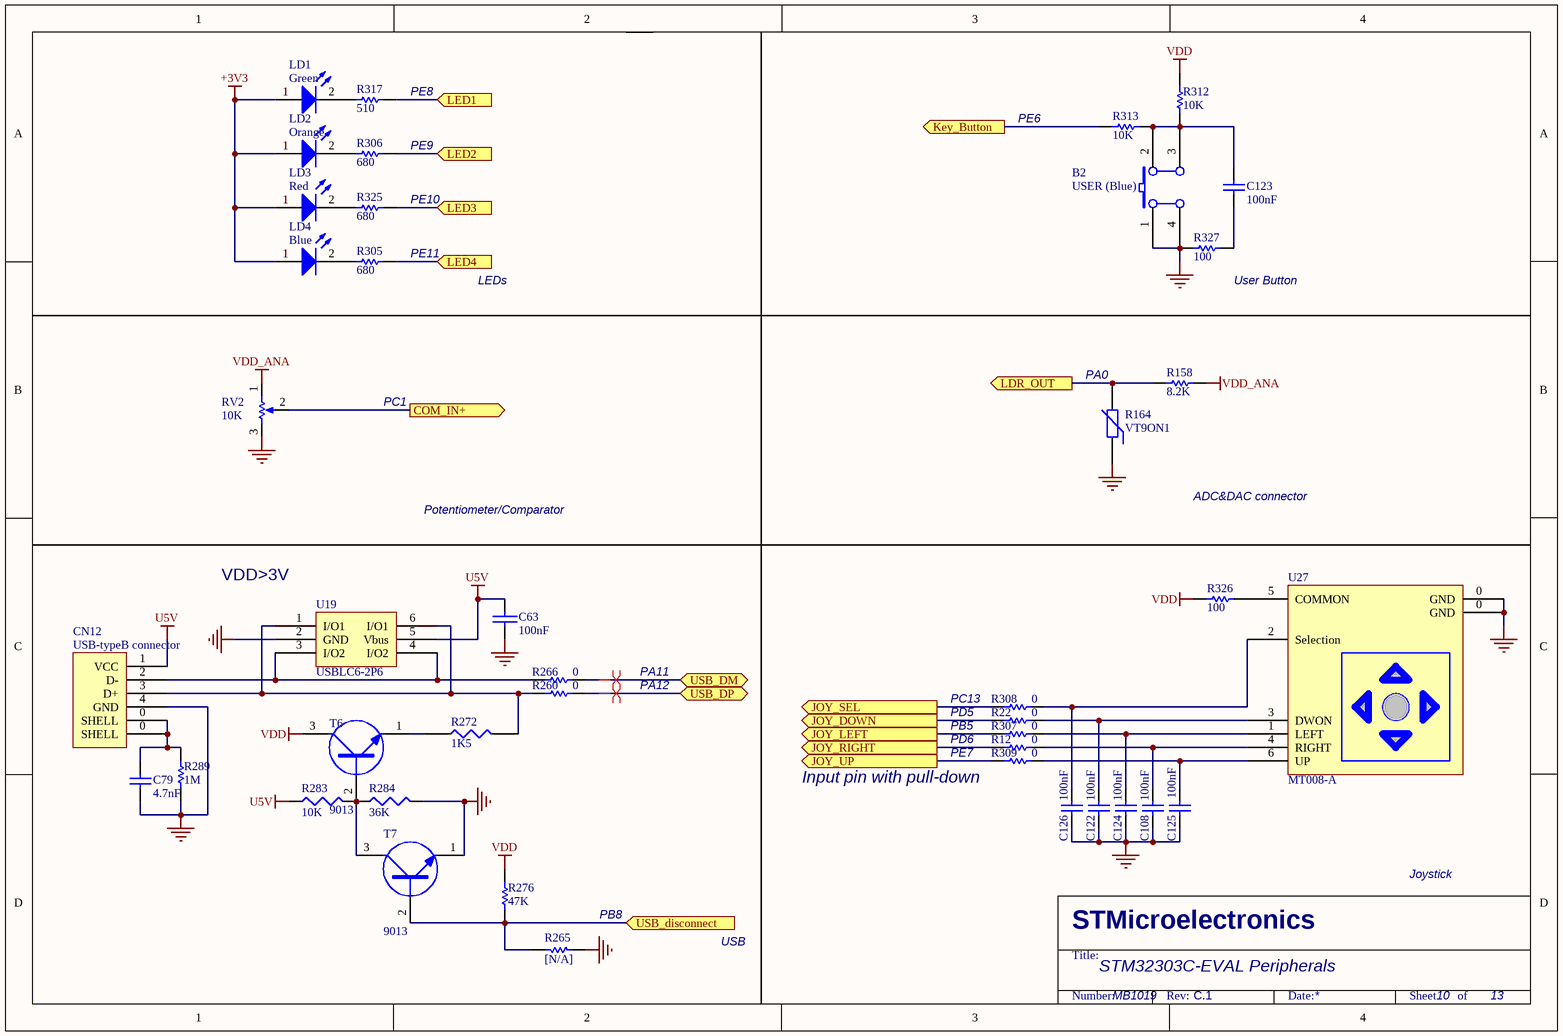
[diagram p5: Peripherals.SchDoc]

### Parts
B2  USER (Blue)  [PB10]
C63  100nF  [0603C]
C79  4.7nF  [0603C]
C108  100nF  [0603C]
C122  100nF  [0603C]
C123  100nF  [0603C]
C124  100nF  [0603C]
C125  100nF  [0603C]
C126  100nF  [0603C]
CN12  USB-typeB connector  [USB-B]
LD1  Green  [0603D]
LD2  Orange  [0603D]
LD3  Red  [0603D]
LD4  Blue  [0603D]
R12  0  [0603R]
R22  0  [0603R]
R158  8.2K  [0603R]
R164  VT9ON1  [PVT901]
R260  0  [0603R]
R265  [N/A]  [0603R]
R266  0  [0603R]
R272  1K5  [0603R]
R276  47K  [0603R]
R283  10K  [0603R]
R284  36K  [0603R]
R289  1M  [0603R]
R305  680  [0603R]
R306  680  [0603R]
R307  0  [0603R]
R308  0  [0603R]
R309  0  [0603R]
R312  10K  [0603R]
R313  10K  [0603R]
R317  510  [0603R]
R325  680  [0603R]
R326  100  [0603R]
R327  100  [0603R]
RV2  10K  [3296W]
T6  9013  [SOT-23]
T7  9013  [SOT-23]
U19  USBLC6-2P6  [SOT-666]
U27  MT008-A  [JOY]

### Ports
COM_IN+ (out), JOY_DOWN (out), JOY_LEFT (out), JOY_RIGHT (out), JOY_SEL (out), JOY_UP (out), Key_Button (out), LDR_OUT (out), LED1 (in), LED2 (in), LED3 (in), LED4 (in), USB_disconnect (in), USB_DM (bidir), USB_DP (bidir)

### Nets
+3V3: LD1.1(A) LD2.1(A) LD3.1(A) LD4.1(A)
GND: B2.1(A0) B2.4(A1) C63.2 C79.1 C108.1 C122.1 C124.1 C125.1 C126.1 CN12.4(GND) R164.1 R265.1 R284.2 R289.1 R327.1 RV2.3(TOP) T7.1(E) U19.2(GND) U27.0(GND)
U5V: C63.1 CN12.1(VCC) R283.1 U19.5(Vbus)
VDD: R276.2 R312.2 R326.1 T6.3(C)
VDD_ANA: R158.2 RV2.1(BOT)
PA11: R266.1 ; port USB_DM
PA12: R260.1 ; port USB_DP
PB5: R307.2 ; port JOY_LEFT
PC13: R308.2 ; port JOY_SEL
PD5: R22.1 ; port JOY_DOWN
PD6: R12.1 ; port JOY_RIGHT
PE7: R309.2 ; port JOY_UP
NetB2_2: B2.2(B0) B2.3(B1) C123.2 R312.1 R313.1
NetC79_2: C79.2 CN12.0(SHELL) R289.2
NetC108_2: C108.2 R12.2 U27.4(RIGHT)
NetC122_2: C122.2 R22.2 U27.3(DWON)
NetC123_1: C123.1 R327.2
NetC124_2: C124.2 R307.1 U27.1(LEFT)
NetC125_2: C125.2 R309.1 U27.6(UP)
NetC126_2: C126.2 R308.1 U27.2(Selection)
NetCN12_2: CN12.2(D-) R266.2 U19.3(I/O2) U19.4(I/O2)
NetCN12_3: CN12.3(D+) R260.2 R272.2 U19.1(I/O1) U19.6(I/O1)
NetLD1_2: LD1.2(K) R317.2
NetLD2_2: LD2.2(K) R306.2
NetLD3_2: LD3.2(K) R325.2
NetLD4_2: LD4.2(K) R305.2
NetR10_2: R158.1 R164.2 ; port LDR_OUT
NetR14_1: RV2.2(TAP) ; port COM_IN+
NetR18_2: R265.2 R276.1 T7.2(B) ; port USB_disconnect
NetR24_1: R317.1 ; port LED1
NetR26_1: R306.1 ; port LED2
NetR28_1: R325.1 ; port LED3
NetR30_1: R305.1 ; port LED4
NetR111_1: R313.2 ; port Key_Button
NetR272_1: R272.1 T6.1(E)
NetR283_2: R283.2 R284.1 T6.2(B) T7.3(C)
NetR326_2: R326.2 U27.5(COMMON)

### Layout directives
differential pair: PA11, PA12

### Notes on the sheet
- (near R317) PE8
- (near R306) PE9
- PE6
- (near R325) PE10
- (near R305) PE11
- LEDs
- (near R327) User Button
- (near R164) PA0
- PC1
- Potentiometer/Comparator
- ADC&DAC connector
- VDD>3V
- PA12
- PA11
- PD5
- PC13
- (near R309) Input pin with pull-down
- PE7
- PD6
- PB5
- (near R265) PB8
- Joystick
- USB
- STM32303C-EVAL Peripherals
- MB1019
- 10
- 13

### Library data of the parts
B2 = SW PUSHBUTTON: SE PUSHBUTTON
C63 = CAP: Capacitor
C79 C108 C122-C126 = CAP: Capacitor; Value: 100pF
CN12 = USB-B
LD1-LD4 = LED2: Typical RED, GREEN, YELLOW, AMBER GaAs LED
R12 R22 R158 R260 R265 R266 R276 R289 R305-R309 R313 R317 R325-R327 = Res1: Resistor; Value: 1K
R164 = Res Varistor: Varistor (Voltage-Sensitive Resistor)
R272 = RES1
R283 R284 = R: Right: 20; Bottom: 30
R312 = res1: Resistor; Value: 1K
RV2 = RV
T6 T7 = NPN
U19 = USBLC6-2
U27 = MT-008A

## Sheet CAN&Humidity_Sensor&HB_LED&IR.SchDoc
size A4; Revision: C.1
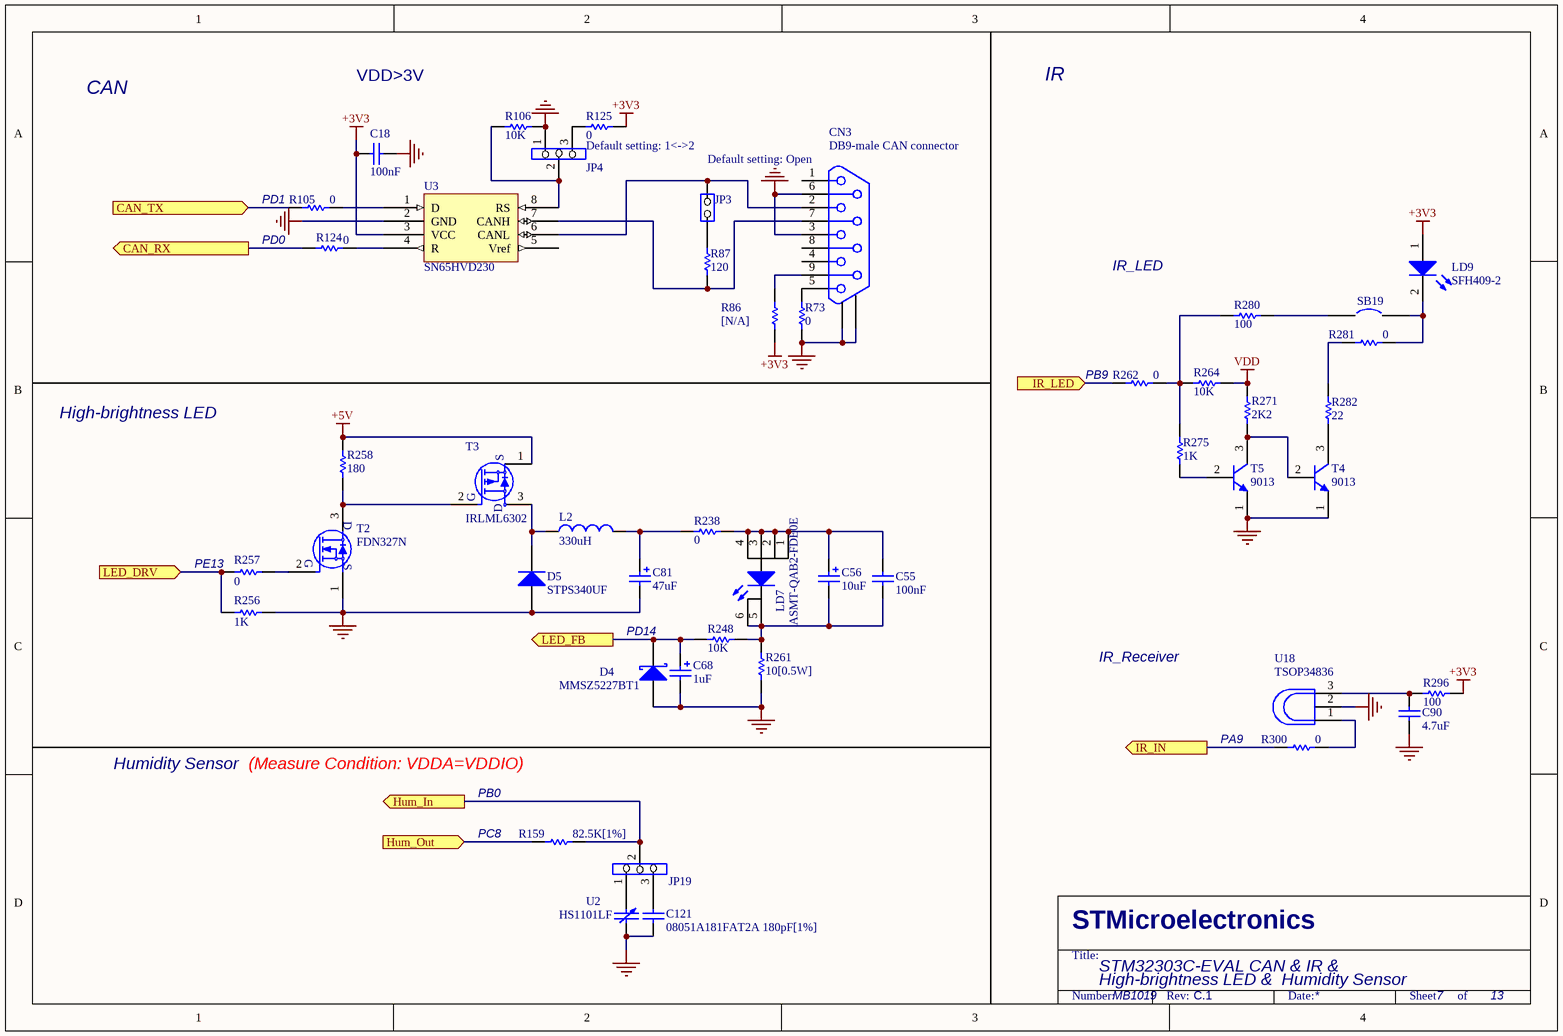
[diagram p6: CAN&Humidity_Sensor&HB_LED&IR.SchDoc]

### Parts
C18  100nF  [0603C]
C55  100nF  [0603C]
C56  10uF  [TAN-A]
C68  1uF  [TAN-A]
C81  47uF  [C200M]
C90  4.7uF  [0603C]
C121  08051A181FAT2A 180pF[1%]  [0805C]
CN3  DB9-male CAN connector  [DB9/M]
D4  MMSZ5227BT1  [SOD-123]
D5  STPS340UF  [SMB]
JP3  (no value)  [SIP2]
JP4  (no value)  [SIP3]
JP19  (no value)  [SIP3]
L2  330uH  [SLF10145]
LD7  ASMT-QAB2-FDE0E  [PLCC4]
LD9  SFH409-2  [D0.1L]
R73  0  [0603R]
R86  [N/A]  [0603R]
R87  120  [0603R]
R105  0  [0603R]
R106  10K  [0603R]
R124  0  [0603R]
R125  0  [0603R]
R159  82.5K[1%]  [0603R]
R238  0  [0603R]
R248  10K  [0603R]
R256  1K  [0603R]
R257  0  [0603R]
R258  180  [0603R]
R261  10[0.5W]  [2010R]
R262  0  [0603R]
R264  10K  [0603R]
R271  2K2  [0603R]
R275  1K  [0603R]
R280  100  [0603R]
R281  0  [0603R]
R282  22  [0603R]
R296  100  [0603R]
R300  0  [0603R]
SB19  (no value)  [JP2_SMD]
T2  FDN327N  [SOT-23]
T3  IRLML6302  [SOT-23]
T4  9013  [SOT-23]
T5  9013  [SOT-23]
U2  HS1101LF  [HS1101LF]
U3  SN65HVD230  [SO8]
U18  TSOP34836  [TSOP348]

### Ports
CAN_RX (out), CAN_TX (in), Hum_In (out), Hum_Out (in), IR_IN (out), IR_LED (in), LED_DRV (in), LED_FB (out)

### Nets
+3V3: C18.2 LD9.1(A) R86.1 R125.2 R296.2 U3.3(VCC)
+5V: R258.1 T3.1(S)
GND: C18.1 C68.2 C81.2 C90.2 C121.1 CN3.0 CN3.3 CN3.6 D4.1(A) D5.1(A) JP4.1 R73.1 R106.2 R256.1 R261.1 T2.1(S) T4.1(E) T5.1(E) U2.2 U3.2(GND) U18.2(GND)
VDD: R264.1 R271.2
PB9: R262.2 ; port IR_LED
PD0: R124.1 ; port CAN_RX
PD1: R105.2 ; port CAN_TX
NetC55_1: C55.1 C56.2 LD7.5(K) LD7.6(K) R248.2 R261.2
NetC55_2: C55.2 C56.1 LD7.1(A) LD7.2(A) LD7.3(A) LD7.4(A) R238.2
NetC68_1: C68.1 D4.2(K) R248.1 ; port LED_FB
NetC81_1: C81.1 L2.2 R238.1
NetC90_1: C90.1 R296.1 U18.3(Vs)
NetC121_2: C121.2 JP19.3
NetCN3_2: CN3.2 JP3.2(NO) U3.6(CANL)
NetCN3_5: CN3.5 R73.2
NetCN3_7: CN3.7 R87.1 U3.7(CANH)
NetCN3_9: CN3.9 R86.2
NetD5_2: D5.2(K) L2.1 T3.3(D)
NetJP3_1: JP3.1(COMMON) R87.2
NetJP4_2: JP4.2 R106.1 U3.8(RS)
NetJP4_3: JP4.3 R125.1
NetJP18_3: R300.1 ; port IR_IN
NetJP19_1: JP19.1 U2.1
NetJP19_2: JP19.2 R159.1 ; port Hum_In
NetLD9_2: LD9.2(K) R281.2 SB19.2
NetR32_1: R256.2 R257.1 ; port LED_DRV
NetR50_1: R159.2 ; port Hum_Out
NetR105_1: R105.1 U3.1(D)
NetR124_2: R124.2 U3.4(R)
NetR257_2: R257.2 T2.2(G)
NetR258_2: R258.2 T2.3(D) T3.2(G)
NetR262_1: R262.1 R264.2 R275.1 R280.2
NetR271_1: R271.1 T4.2(B) T5.3(C)
NetR275_2: R275.2 T5.2(B)
NetR280_1: R280.1 SB19.1
NetR281_1: R281.1 R282.2
NetR282_1: R282.1 T4.3(C)
NetR300_2: R300.2 U18.1(OUT)

Not connected (* = marked no-connect by the designer): CN3 1 4 8; U3 5(Vref)

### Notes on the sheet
- CAN
- VDD>3V
- IR
- Default setting: 1<->2
- (near CN3) Default setting: Open
- (near R105) PD1
- PD0
- IR_LED
- (near R262) PB9
- High-brightness LED
- (near R257) PE13
- PD14
- IR_Receiver
- Humidity Sensor
- (Measure Condition: VDDA=VDDIO)
- PA9
- PB0
- (near R159) PC8
- High-brightness LED &  Humidity Sensor
- STM32303C-EVAL CAN & IR &
- MB1019
- 7
- 13

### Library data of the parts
C18 = CAP: Capacitor
C55 C90 C121 = Cap: Capacitor; Value: 10nF
C56 = Cap Pol1: Polarized Capacitor (Radial)
C68 C81 = Cap Pol1: Polarized Capacitor (Radial); Value: 10uF
CN3 = DB9
D4 = D Schottky: Schottky Diode; Code - JEDEC: DO-214-AA
D5 = STPS340: Default Diode; Code - JEDEC: DO-214-AB
JP3 = JP2
JP4 JP19 = Jumper3
L2 = SLF10145T-331MR54-PF: Inductor; Value: 100uH
LD7 = HB_LED: High brightness LED
LD9 = LED2: as LD1 on sheet Peripherals
R73 R86 R87 R105 R106 R125 R238 R248 R262 = res1: Resistor; Value: 1K
R124 R159 R257 R258 R261 R264 R271 R280-R282 R296 R300 = Res1: Resistor; Value: 1K
R256 R275 = Res1: Resistor
SB19 = Circuit Breaker
T2 = 2N7000
T4 T5 = NPN: NPN Bipolar Transistor; Code - JEDEC: TO-226-AA
U3 = SN65HVD230D
U18 = TSOP34838

## Sheet JTAG&Trace.SchDoc
size A4; Revision: C.1
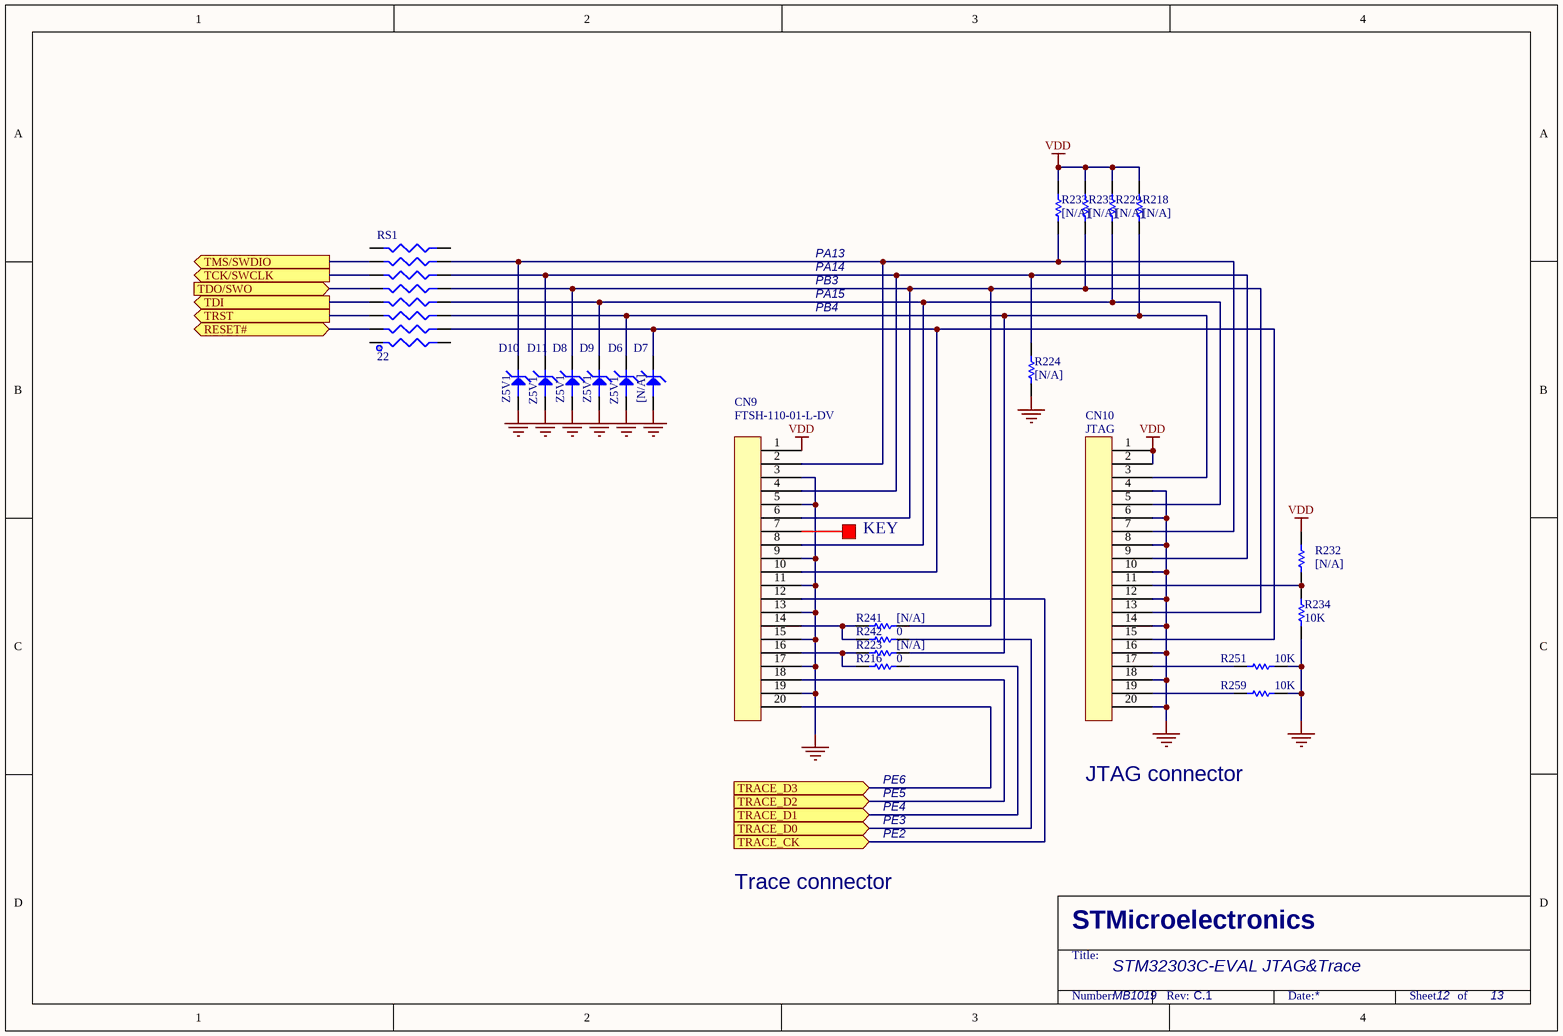
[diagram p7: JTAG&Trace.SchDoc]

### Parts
CN9  FTSH-110-01-L-DV  [FTSH-110-01-L-DV]
CN10  JTAG  [IDC20S]
D6  Z5V1  [SOT-23]
D7  [N/A]  [SOT-23]
D8  Z5V1  [SOT-23]
D9  Z5V1  [SOT-23]
D10  Z5V1  [SOT-23]
D11  Z5V1  [SOT-23]
R216  0  [0603R]
R218  [N/A]  [0603R]
R223  [N/A]  [0603R]
R224  [N/A]  [0603R]
R229  [N/A]  [0603R]
R232  [N/A]  [0603R]
R233  [N/A]  [0603R]
R234  10K  [0603R]
R235  [N/A]  [0603R]
R241  [N/A]  [0603R]
R242  0  [0603R]
R251  10K  [0603R]
R259  10K  [0603R]
RS1  22  [RES8B_0402]

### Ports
RESET# (bidir), TCK/SWCLK (out), TDI (out), TDO/SWO (in), TMS/SWDIO (out), TRACE_CK (in), TRACE_D0 (in), TRACE_D1 (in), TRACE_D2 (in), TRACE_D3 (in), TRST (out)

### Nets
GND: CN9.3 CN9.5 CN9.9 CN9.11 CN9.13 CN9.15 CN9.17 CN9.19 CN10.4 CN10.6 CN10.8 CN10.10 CN10.12 CN10.14 CN10.16 CN10.18 CN10.20 D6.2 D7.2 D8.2 D9.2 D10.2 D11.2 R224.1 R234.1 R251.1 R259.1
VDD: CN9.1 CN10.1 CN10.2 R218.2 R229.2 R232.2 R233.2 R235.2
PA13: RS1.13 ; port TMS/SWDIO
PA14: RS1.11 ; port TCK/SWCLK
PA15: RS1.7 ; port TDI
PB3: RS1.9 ; port TDO/SWO
PB4: RS1.5 ; port TRST
PE6: CN9.20 ; port TRACE_D3
RESET#: RS1.3 ; port RESET#
NetCN9_2: CN9.2 CN10.7 D10.3 R233.1 RS1.14
NetCN9_4: CN9.4 CN10.9 D11.3 R224.2 RS1.12
NetCN9_6: CN9.6 CN10.13 D8.3 R235.1 R241.2 RS1.10
NetCN9_8: CN9.8 CN10.5 D9.3 R229.1 RS1.8
NetCN9_10: CN9.10 CN10.15 D7.3 RS1.4
NetCN9_12: CN9.12 ; port TRACE_CK
NetCN9_14: CN9.14 R241.1 R242.1
NetCN9_16: CN9.16 R216.1 R223.1
NetCN9_18: CN9.18 ; port TRACE_D2
NetCN10_3: CN10.3 D6.3 R218.1 R223.2 RS1.6
NetCN10_11: CN10.11 R232.1 R234.2
NetCN10_17: CN10.17 R251.2
NetCN10_19: CN10.19 R259.2
NetR4_1: R242.2 ; port TRACE_D0
NetR6_1: R216.2 ; port TRACE_D1

Not connected (* = marked no-connect by the designer): CN9 7; RS1 1 2 15 16

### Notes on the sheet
- PA13
- PA14
- PB3
- PA15
- PB4
- KEY
- PE6
- JTAG connector
- PE5
- PE4
- PE3
- PE2
- Trace connector
- STM32303C-EVAL JTAG&Trace
- MB1019
- 12
- 13

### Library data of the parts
CN9 CN10 = 20PIN1
D6-D11 = BATS5V6
R216 R218 R223 R224 R229 R232-R235 R241 R242 R251 R259 = Res1: Resistor; Value: 1K
RS1 = RES8B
